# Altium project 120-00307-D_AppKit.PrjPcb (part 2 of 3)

## Sheet 6-GPIOTranslate.SchDoc: APP KIT BOARD
size 431 x 279 mm; Organization: ORGANIZATION; Address1: ADDRESS 1; Address2: ADDRESS 2; Address3: ADDRESS 3; Address4: ADDRESS 4; DocumentNumber: 6; Revision: -; SheetNumber: 6; SheetTotal: 14; ENG_APP_DATE: --/--/--; DSN_APP_DATE: --/--/--; CHK_APP_DATE: --/--/--
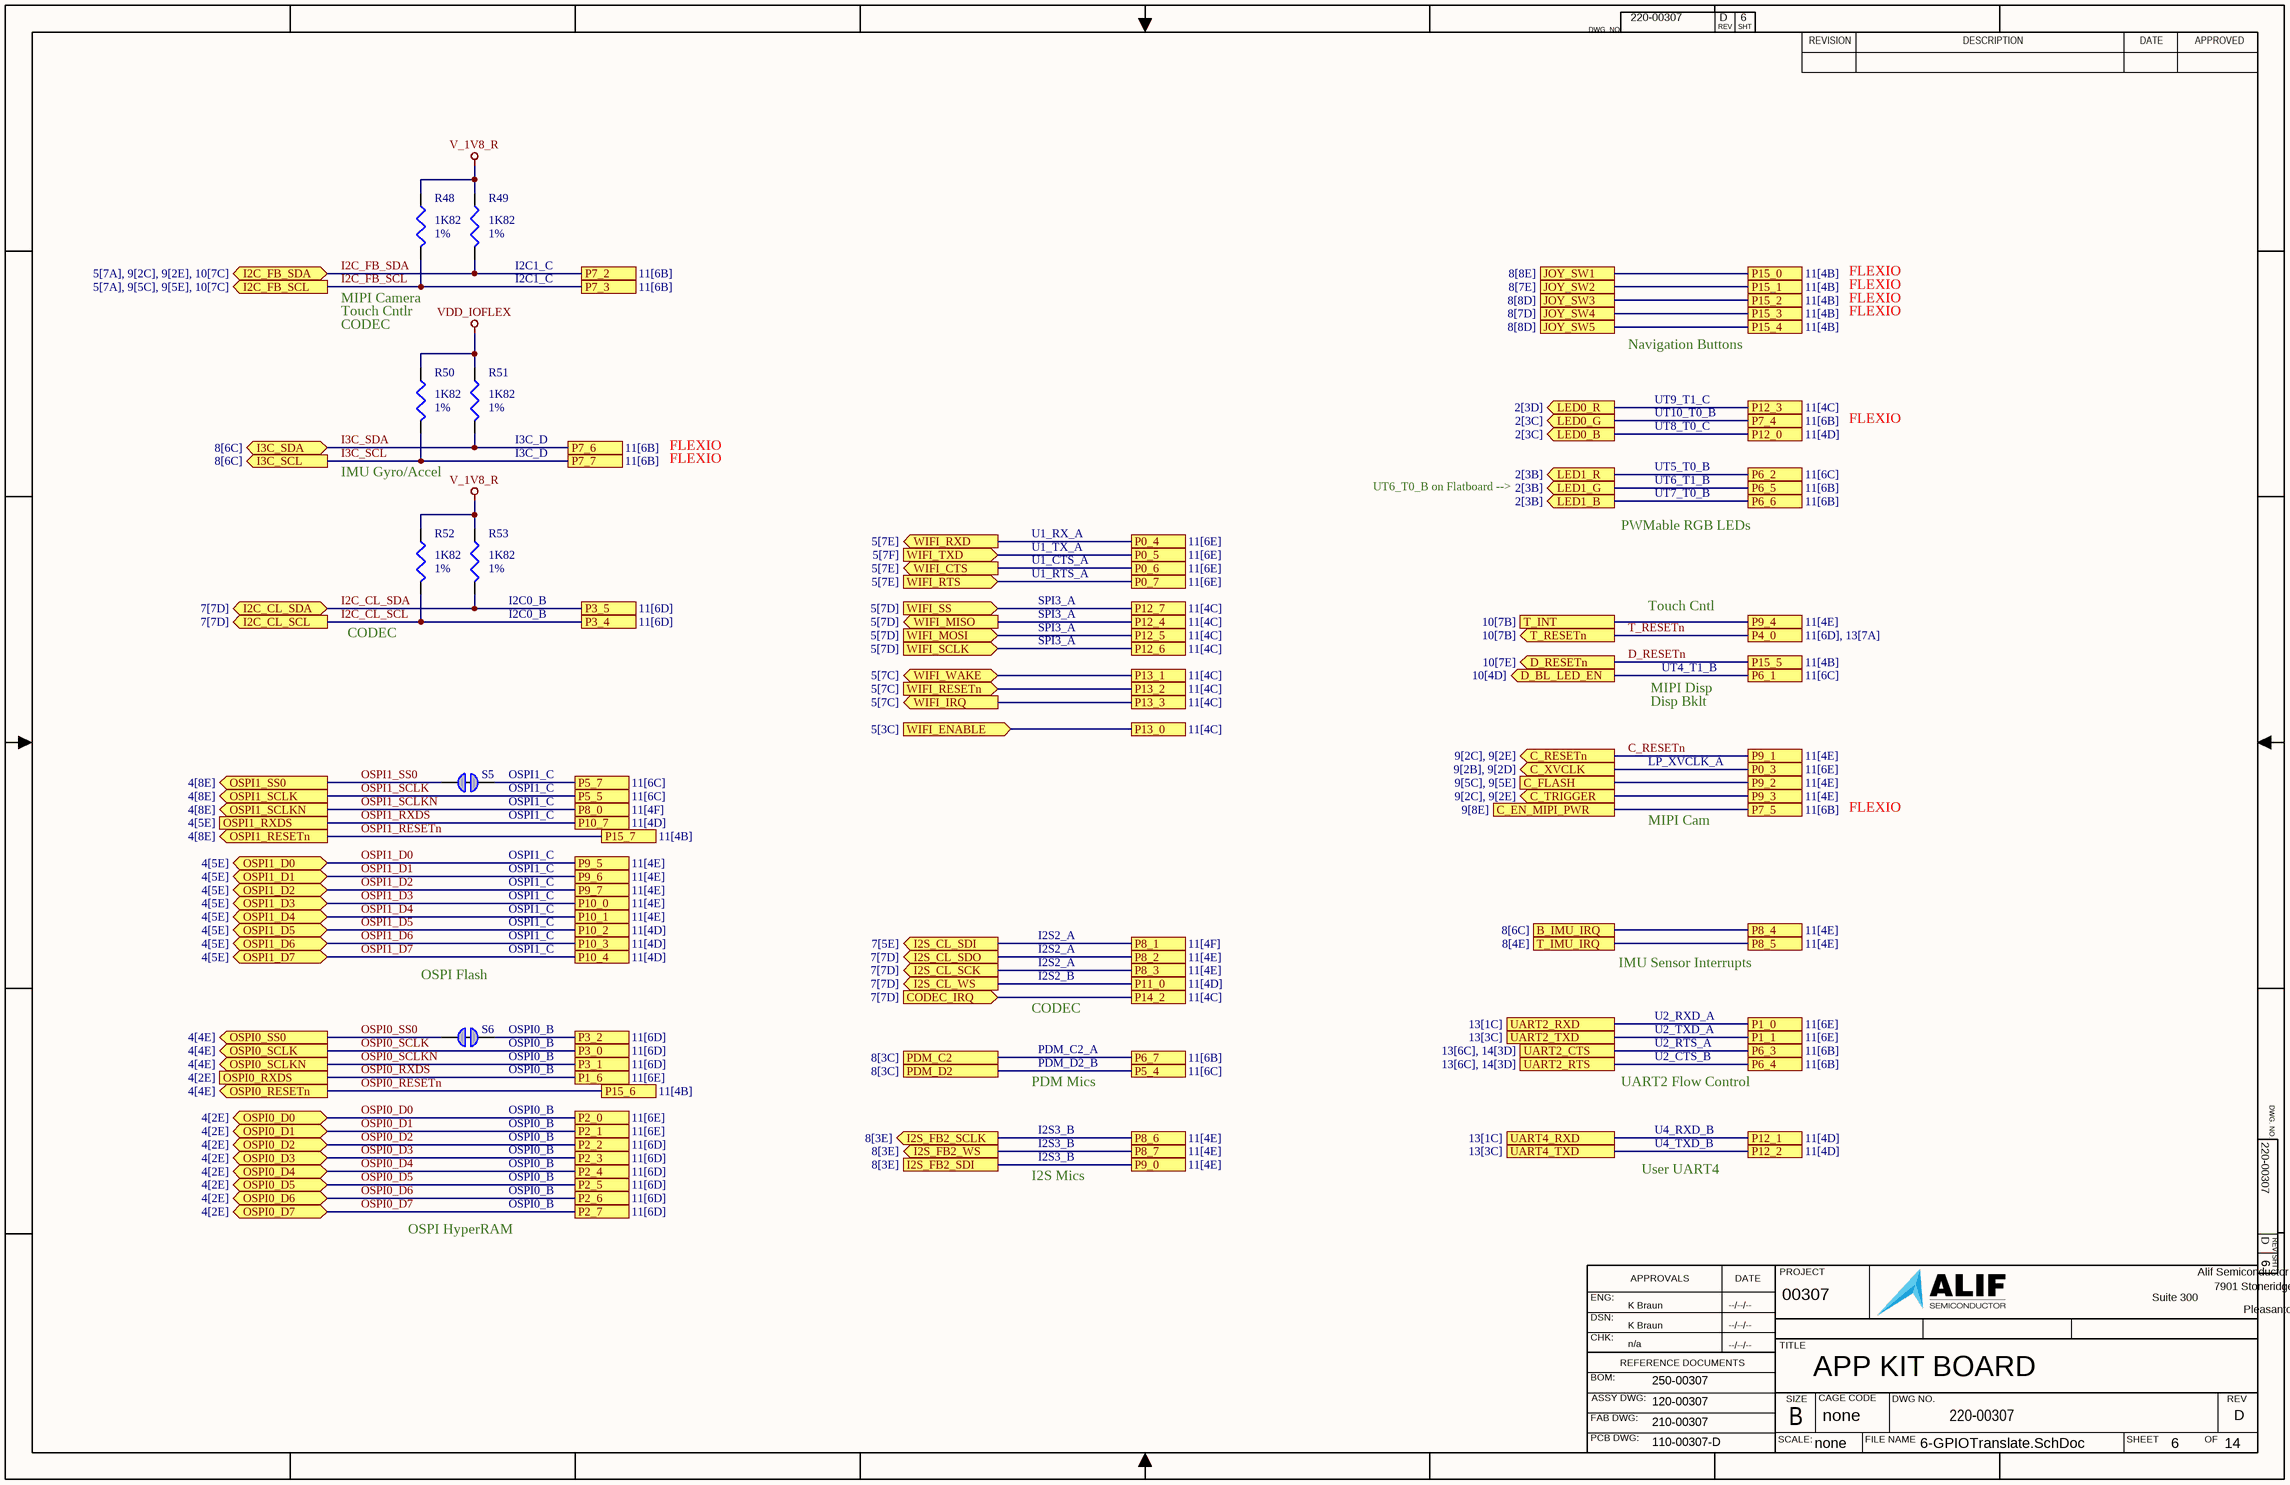
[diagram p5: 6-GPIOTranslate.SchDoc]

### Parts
R48  value 1K82  Tolerance: 1%  [RESC0402-01]  (hidden comment: Res3)
R49  value 1K82  Tolerance: 1%  [RESC0402-01]  (hidden comment: Res3)
R50  value 1K82  Tolerance: 1%  [RESC0402-01]  (hidden comment: Res3)
R51  value 1K82  Tolerance: 1%  [RESC0402-01]  (hidden comment: Res3)
R52  value 1K82  Tolerance: 1%  [RESC0402-01]  (hidden comment: Res3)
R53  value 1K82  Tolerance: 1%  [RESC0402-01]  (hidden comment: Res3)
S5  SolderJumperShorted_Small  [Solderbridge_Shorted]  (value not drawn)  (net tie, no BOM)
S6  SolderJumperShorted_Small  [Solderbridge_Shorted]  (value not drawn)  (net tie, no BOM)

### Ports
B_IMU_IRQ (see 8[6C]), C_EN_MIPI_PWR (see 9[8E]), C_FLASH (see 9[5C], 9[5E]), C_RESETn (out, see 9[2C], 9[2E]), C_TRIGGER (out, see 9[2C], 9[2E]), C_XVCLK (out, see 9[2B], 9[2D]), CODEC_IRQ (in, see 7[7D]), D_BL_LED_EN (out, see 10[4D]), D_RESETn (out, see 10[7E]), I2C_CL_SCL (out, see 7[7D]), I2C_CL_SDA (bidir, see 7[7D]), I2C_FB_SCL (out, see 5[7A], 9[5C], 9[5E], 10[7C]), I2C_FB_SDA (bidir, see 5[7A], 9[2C], 9[2E], 10[7C]), I2S_CL_SCK (out, see 7[7D]), I2S_CL_SDI (out, see 7[5E]), I2S_CL_SDO (out, see 7[7D]), I2S_CL_WS (out, see 7[7D]), I2S_FB2_SCLK (out, see 8[3E]), I2S_FB2_SDI (see 8[3E]), I2S_FB2_WS (out, see 8[3E]), I3C_SCL (out, see 8[6C]), I3C_SDA (bidir, see 8[6C]), JOY_SW1 (see 8[8E]), JOY_SW2 (see 8[7E]), JOY_SW3 (see 8[8D]), JOY_SW4 (see 8[7D]), JOY_SW5 (see 8[8D]), LED0_B (out, see 2[3C]), LED0_G (out, see 2[3C]), LED0_R (out, see 2[3D]), LED1_B (out, see 2[3B]), LED1_G (out, see 2[3B]), LED1_R (out, see 2[3B]), OSPI0_D0 (bidir, see 4[2E]), OSPI0_D1 (bidir, see 4[2E]), OSPI0_D2 (bidir, see 4[2E]), OSPI0_D3 (bidir, see 4[2E]), OSPI0_D4 (bidir, see 4[2E]), OSPI0_D5 (bidir, see 4[2E]), OSPI0_D6 (bidir, see 4[2E]), OSPI0_D7 (bidir, see 4[2E]), OSPI0_RESETn (out, see 4[4E]), OSPI0_RXDS (see 4[2E]), OSPI0_SCLK (out, see 4[4E]), OSPI0_SCLKN (out, see 4[4E]), OSPI0_SS0 (out, see 4[4E]), OSPI1_D0 (bidir, see 4[5E]), OSPI1_D1 (bidir, see 4[5E]), OSPI1_D2 (bidir, see 4[5E]), OSPI1_D3 (bidir, see 4[5E]), OSPI1_D4 (bidir, see 4[5E]), OSPI1_D5 (bidir, see 4[5E]), OSPI1_D6 (bidir, see 4[5E]), OSPI1_D7 (bidir, see 4[5E]), OSPI1_RESETn (out, see 4[8E]), OSPI1_RXDS (see 4[5E]), OSPI1_SCLK (out, see 4[8E]), OSPI1_SCLKN (out, see 4[8E]), OSPI1_SS0 (out, see 4[8E]), P0_3 (see 11[6E]), P0_4 (see 11[6E]), P0_5 (see 11[6E]), P0_6 (see 11[6E]), P0_7 (see 11[6E]), P1_0 (see 11[6E]), P1_1 (see 11[6E]), P1_6 (see 11[6E]), P2_0 (see 11[6E]), P2_1 (see 11[6E]), P2_2 (see 11[6D]), P2_3 (see 11[6D]), P2_4 (see 11[6D]), P2_5 (see 11[6D]), P2_6 (see 11[6D]), P2_7 (see 11[6D]), P3_0 (see 11[6D]), P3_1 (see 11[6D]), P3_2 (see 11[6D]), P3_4 (see 11[6D]), P3_5 (see 11[6D]), P4_0 (see 11[6D], 13[7A]), P5_4 (see 11[6C]), P5_5 (see 11[6C]), P5_7 (see 11[6C]), P6_1 (see 11[6C]), P6_2 (see 11[6C]), P6_3 (see 11[6B]), P6_4 (see 11[6B]), P6_5 (see 11[6B]), P6_6 (see 11[6B]), P6_7 (see 11[6B]), P7_2 (see 11[6B]), P7_3 (see 11[6B]), P7_4 (see 11[6B]), P7_5 (see 11[6B]), P7_6 (see 11[6B]), P7_7 (see 11[6B]), P8_0 (see 11[4F]), P8_1 (see 11[4F]), P8_2 (see 11[4E]), P8_3 (see 11[4E]), P8_4 (see 11[4E]), P8_5 (see 11[4E]), P8_6 (see 11[4E]), P8_7 (see 11[4E]), P9_0 (see 11[4E]), P9_1 (see 11[4E]), P9_2 (see 11[4E]), P9_3 (see 11[4E]), P9_4 (see 11[4E]), P9_5 (see 11[4E]), P9_6 (see 11[4E]), P9_7 (see 11[4E]), P10_0 (see 11[4E]), P10_1 (see 11[4E]), P10_2 (see 11[4D]), P10_3 (see 11[4D]), P10_4 (see 11[4D]), P10_7 (see 11[4D]), P11_0 (see 11[4D]), P12_0 (see 11[4D]), P12_1 (see 11[4D]), P12_2 (see 11[4D]), P12_3 (see 11[4C]), P12_4 (see 11[4C]), P12_5 (see 11[4C]), P12_6 (see 11[4C]), P12_7 (see 11[4C]), P13_0 (see 11[4C]), P13_1 (see 11[4C]), P13_2 (see 11[4C]), P13_3 (see 11[4C]), P14_2 (see 11[4C]), P15_0 (see 11[4B]), P15_1 (see 11[4B]), P15_2 (see 11[4B]), P15_3 (see 11[4B]), P15_4 (see 11[4B]), P15_5 (see 11[4B]), P15_6 (see 11[4B]), P15_7 (see 11[4B]), PDM_C2 (see 8[3C]), PDM_D2 (see 8[3C]), T_IMU_IRQ (see 8[4E]), T_INT (see 10[7B]), T_RESETn (out, see 10[7B]), UART2_CTS (see 13[6C], 14[3D]), UART2_RTS (see 13[6C], 14[3D]), UART2_RXD (see 13[1C]), UART2_TXD (see 13[3C]), UART4_RXD (see 13[1C]), UART4_TXD (see 13[3C]), WIFI_CTS (out, see 5[7E]), WIFI_ENABLE (in, see 5[3C]), WIFI_IRQ (out, see 5[7C]), WIFI_MISO (out, see 5[7D]), WIFI_MOSI (in, see 5[7D]), WIFI_RESETn (in, see 5[7C]), WIFI_RTS (in, see 5[7E]), WIFI_RXD (out, see 5[7E]), WIFI_SCLK (in, see 5[7D]), WIFI_SS (in, see 5[7D]), WIFI_TXD (in, see 5[7F]), WIFI_WAKE (bidir, see 5[7C])

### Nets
V_1V8_R: R48.1 R49.1 R52.1 R53.1
VDD_IOFLEX: R50.1 R51.1
C_EN_MIPI_PWR: port C_EN_MIPI_PWR, port P7_5
C_RESETn: port C_RESETn, port P9_1
D_RESETn: port D_RESETn, port P15_5
I2C_CL_SCL: R52.2 ; port P3_4, port I2C_CL_SCL
I2C_CL_SDA: R53.2 ; port I2C_CL_SDA, port P3_5
I2C_FB_SCL: R48.2 ; port P7_3, port I2C_FB_SCL
I2C_FB_SDA: R49.2 ; port I2C_FB_SDA, port P7_2
I3C_SCL: R50.2 ; port I3C_SCL, port P7_7
I3C_SDA: R51.2 ; port I3C_SDA, port P7_6
OSPI0_D0: port OSPI0_D0, port P2_0
OSPI0_D1: port OSPI0_D1, port P2_1
OSPI0_D2: port OSPI0_D2, port P2_2
OSPI0_D3: port OSPI0_D3, port P2_3
OSPI0_D4: port OSPI0_D4, port P2_4
OSPI0_D5: port OSPI0_D5, port P2_5
OSPI0_D6: port OSPI0_D6, port P2_6
OSPI0_D7: port OSPI0_D7, port P2_7
OSPI0_RESETn: port OSPI0_RESETn, port P15_6
OSPI0_RXDS: port OSPI0_RXDS, port P1_6
OSPI0_SCLK: port OSPI0_SCLK, port P3_0
OSPI0_SCLKN: port OSPI0_SCLKN, port P3_1
OSPI0_SS0: S6.1 ; port OSPI0_SS0
OSPI1_D0: port OSPI1_D0, port P9_5
OSPI1_D1: port OSPI1_D1, port P9_6
OSPI1_D2: port OSPI1_D2, port P9_7
OSPI1_D3: port OSPI1_D3, port P10_0
OSPI1_D4: port OSPI1_D4, port P10_1
OSPI1_D5: port OSPI1_D5, port P10_2
OSPI1_D6: port OSPI1_D6, port P10_3
OSPI1_D7: port OSPI1_D7, port P10_4
OSPI1_RESETn: port OSPI1_RESETn, port P15_7
OSPI1_RXDS: port OSPI1_RXDS, port P10_7
OSPI1_SCLK: port OSPI1_SCLK, port P5_5
OSPI1_SCLKN: port OSPI1_SCLKN, port P8_0
OSPI1_SS0: S5.1 ; port OSPI1_SS0
P0_3: port C_XVCLK, port P0_3
P0_4: port P0_4, port WIFI_RXD
P0_5: port P0_5, port WIFI_TXD
P0_6: port P0_6, port WIFI_CTS
P0_7: port P0_7, port WIFI_RTS
P1_0: port UART2_RXD, port P1_0
P1_1: port UART2_TXD, port P1_1
P3_2: S6.2 ; port P3_2
P5_4: port PDM_D2, port P5_4
P5_7: S5.2 ; port P5_7
P6_1: port D_BL_LED_EN, port P6_1
P6_2: port LED1_R, port P6_2
P6_3: port UART2_CTS, port P6_3
P6_4: port UART2_RTS, port P6_4
P6_5: port LED1_G, port P6_5
P6_6: port LED1_B, port P6_6
P6_7: port PDM_C2, port P6_7
P7_4: port LED0_G, port P7_4
P8_1: port I2S_CL_SDI, port P8_1
P8_2: port I2S_CL_SDO, port P8_2
P8_3: port I2S_CL_SCK, port P8_3
P8_4: port B_IMU_IRQ, port P8_4
P8_5: port T_IMU_IRQ, port P8_5
P8_6: port I2S_FB2_SCLK, port P8_6
P8_7: port I2S_FB2_WS, port P8_7
P9_0: port I2S_FB2_SDI, port P9_0
P9_2: port C_FLASH, port P9_2
P9_3: port C_TRIGGER, port P9_3
P9_4: port T_INT, port P9_4
P11_0: port I2S_CL_WS, port P11_0
P12_0: port LED0_B, port P12_0
P12_1: port UART4_RXD, port P12_1
P12_2: port UART4_TXD, port P12_2
P12_3: port LED0_R, port P12_3
P12_4: port WIFI_MISO, port P12_4
P12_5: port WIFI_MOSI, port P12_5
P12_6: port WIFI_SCLK, port P12_6
P12_7: port WIFI_SS, port P12_7
P13_0: port WIFI_ENABLE, port P13_0
P13_1: port WIFI_WAKE, port P13_1
P13_2: port WIFI_RESETn, port P13_2
P13_3: port WIFI_IRQ, port P13_3
P14_2: port CODEC_IRQ, port P14_2
P15_0: port JOY_SW1, port P15_0
P15_1: port JOY_SW2, port P15_1
P15_2: port JOY_SW3, port P15_2
P15_3: port JOY_SW4, port P15_3
P15_4: port JOY_SW5, port P15_4
T_RESETn: port T_RESETn, port P4_0  [project net P4_0]

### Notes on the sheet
- MIPI Camera
- (near R49) I2C1_C
- FLEXIO
- Touch Cntlr
- CODEC
- Navigation Buttons
- UT10_T0_B
- UT9_T1_C
- UT8_T0_C
- IMU Gyro/Accel
- (near R51) I3C_D
- UT6_T0_B on Flatboard -->
- UT5_T0_B
- UT6_T1_B
- UT7_T0_B
- U1_CTS_A
- U1_RX_A
- U1_TX_A
- PWMable RGB LEDs
- (near R53) I2C0_B
- U1_RTS_A
- SPI3_A
- Touch Cntl
- MIPI Disp
- UT4_T1_B
- LP_XVCLK_A
- Disp Bklt
- (near S5) OSPI1_C
- MIPI Cam
- OSPI1_C
- I2S2_A
- IMU Sensor Interrupts
- OSPI Flash
- (near S6) OSPI0_B
- I2S2_B
- U2_RXD_A
- U2_TXD_A
- PDM Mics
- PDM_C2_A
- PDM_D2_B
- UART2 Flow Control
- U2_CTS_B
- U2_RTS_A
- OSPI0_B
- I2S3_B
- U4_RXD_B
- U4_TXD_B
- OSPI HyperRAM
- I2S Mics
- User UART4

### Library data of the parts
R48-R53 = Res3: Res,1K82,1%,100ppm,0402; Manufacturer 1: Stackpol; Manufacturer Part Number 1: RMCF0402FT1K82; Wattage: 63mW
S5 S6 = SolderJumperShorted_Small: DNI,Solderable Jumper,Shorted; Wattage: 63mW; PCB_Footprint: SSHORTED

## Sheet 7-CODEC.SchDoc: APP KIT BOARD
size 431 x 279 mm; Organization: ORGANIZATION; Address1: ADDRESS 1; Address2: ADDRESS 2; Address3: ADDRESS 3; Address4: ADDRESS 4; DocumentNumber: 7; Revision: -; SheetNumber: 7; SheetTotal: 14; ENG_APP_DATE: --/--/--; DSN_APP_DATE: --/--/--; CHK_APP_DATE: --/--/--
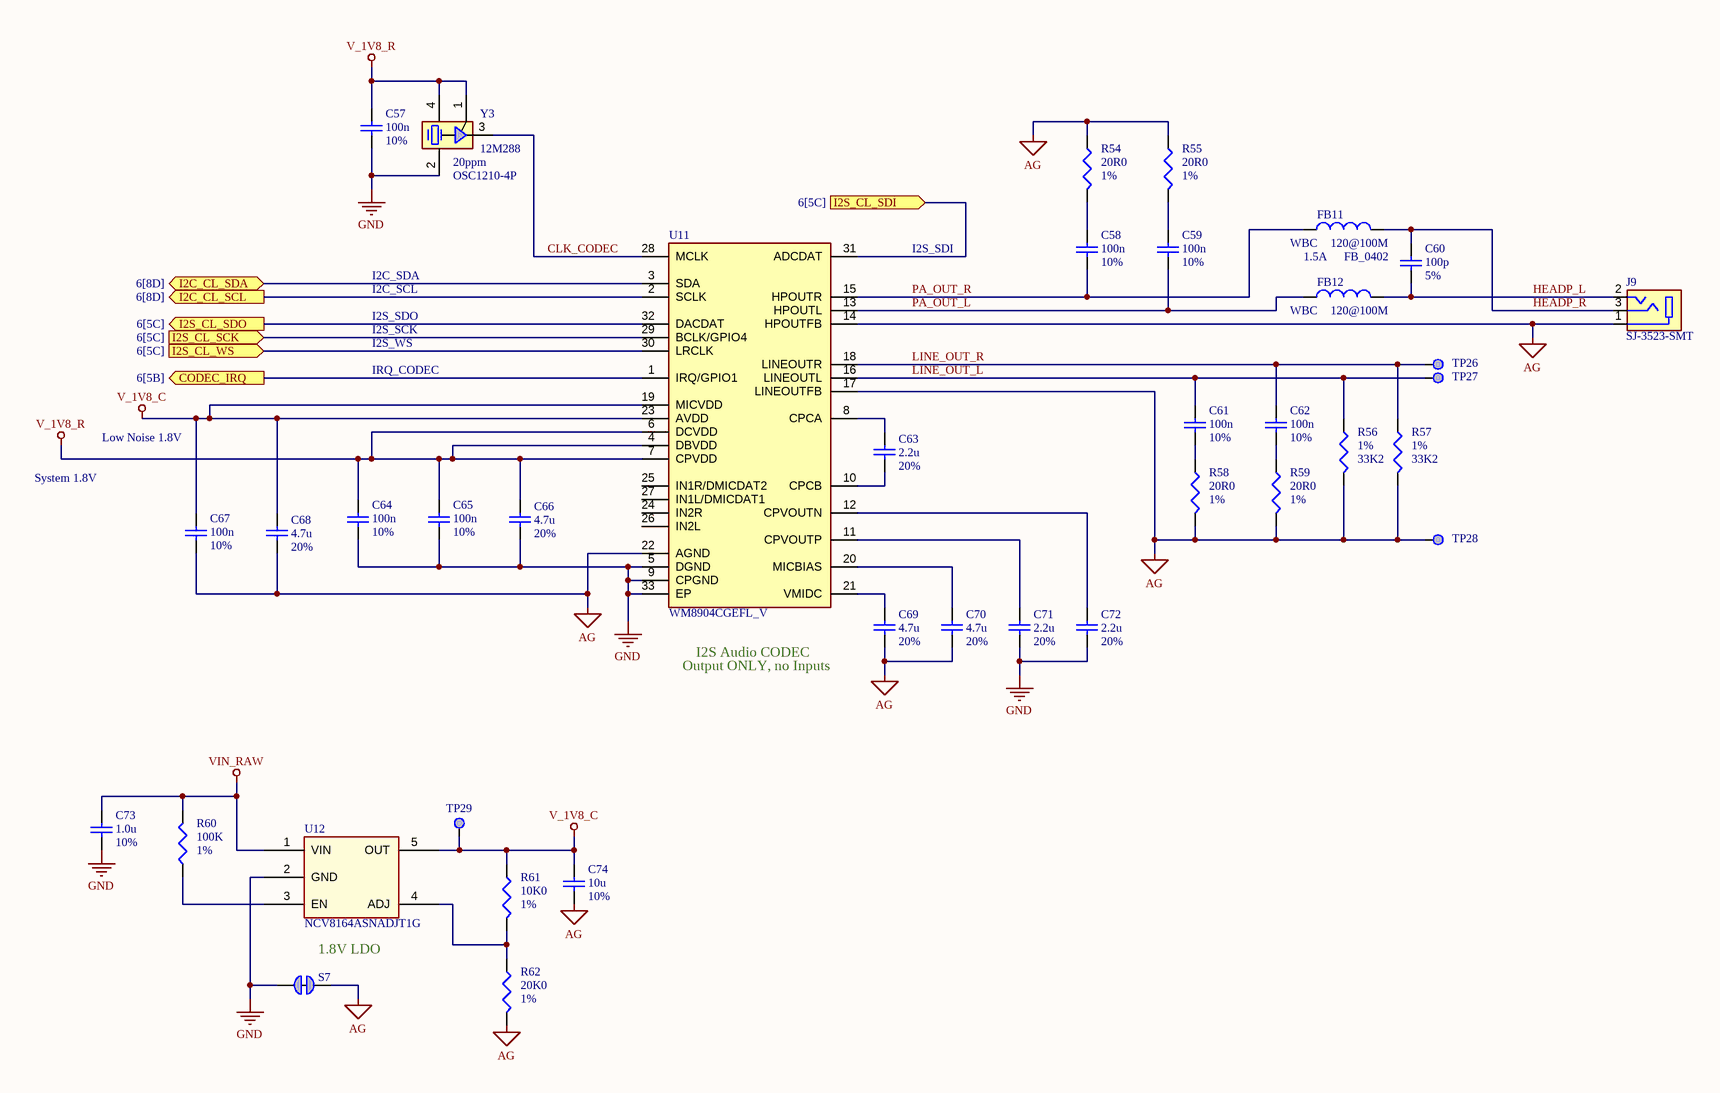
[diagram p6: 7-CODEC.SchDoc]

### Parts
C57  value 100n  Tolerance: 10%  [CAPC0402-01]  (hidden comment: Cap)
C58  value 100n  Tolerance: 10%  [CAPC0402-01]  (hidden comment: Cap)
C59  value 100n  Tolerance: 10%  [CAPC0402-01]  (hidden comment: Cap)
C60  value 100p  Tolerance: 5%  [CAPC0402-01]  (hidden comment: Cap)
C61  value 100n  Tolerance: 10%  [CAPC0402-01]  (hidden comment: Cap)
C62  value 100n  Tolerance: 10%  [CAPC0402-01]  (hidden comment: Cap)
C63  value 2.2u  Tolerance: 20%  [CAPC0402-01]  (hidden comment: Cap_225M25VX5R0402_1)
C64  value 100n  Tolerance: 10%  [CAPC0402-01]  (hidden comment: Cap)
C65  value 100n  Tolerance: 10%  [CAPC0402-01]  (hidden comment: Cap)
C66  value 4.7u  Tolerance: 20%  [CAPC0402-01]  (hidden comment: Cap)
C67  value 100n  Tolerance: 10%  [CAPC0402-01]  (hidden comment: Cap)
C68  value 4.7u  Tolerance: 20%  [CAPC0402-01]  (hidden comment: Cap)
C69  value 4.7u  Tolerance: 20%  [CAPC0402-01]  (hidden comment: Cap)
C70  value 4.7u  Tolerance: 20%  [CAPC0402-01]  (hidden comment: Cap)
C71  value 2.2u  Tolerance: 20%  [CAPC0402-01]  (hidden comment: Cap_225M25VX5R0402_1)
C72  value 2.2u  Tolerance: 20%  [CAPC0402-01]  (hidden comment: Cap_225M25VX5R0402_1)
C73  value 1.0u  Tolerance: 10%  [CAPC0402-01]  (hidden comment: Cap)
C74  value 10u  Tolerance: 10%  [CAPC0402-01]  (hidden comment: Cap)
FB11  value WBC  Impedance: 120@100M  RMS_Current: 1.5A  [FB_0402]  (hidden comment: Inductor)
FB12  value WBC  Impedance: 120@100M  [FB_0402]  (hidden comment: Inductor)
J9  SJ-3523-SMT  [CONN_CUI_SJ-3523-SMT-TR]
R54  value 20R0  Tolerance: 1%  [RESC0402-01]  (hidden comment: Res3)
R55  value 20R0  Tolerance: 1%  [RESC0402-01]  (hidden comment: Res3)
R56  value 33K2  Tolerance: 1%  [RESC0402-01]  (hidden comment: Res3)
R57  value 33K2  Tolerance: 1%  [RESC0402-01]  (hidden comment: Res3)
R58  value 20R0  Tolerance: 1%  [RESC0402-01]  (hidden comment: Res3)
R59  value 20R0  Tolerance: 1%  [RESC0402-01]  (hidden comment: Res3)
R60  value 100K  Tolerance: 1%  [RESC0402-01]  (hidden comment: Res3)
R61  value 10K0  Tolerance: 1%  [RESC0402-01]  (hidden comment: Res3)
R62  value 20K0  Tolerance: 1%  [RESC0402-01]  (hidden comment: Res3)
S7  SolderJumperShorted_Small  [Solderbridge_Shorted]  (value not drawn)  (net tie, no BOM)
TP26  TP_SMPAD  [TP_30_RND]  (value not drawn)  (no BOM)
TP27  TP_SMPAD  [TP_30_RND]  (value not drawn)  (no BOM)
TP28  TP_SMPAD  [TP_30_RND]  (value not drawn)  (no BOM)
TP29  TP_SMPAD  [TP_30_RND]  (value not drawn)  (no BOM)
U11  WM8904CGEFL_V  [QFN40P400X400X80-33N]
U12  NCV8164ASNADJT1G  [TSOT23-5_ONS]
Y3  value 12M288  Tolerance: 20ppm  PCB_Footprint: OSC1210-4P  [OSC_4P_3225_1210_uChip_DSC1001DL5]  (hidden comment: XO_12M288)

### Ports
CODEC_IRQ (out, see 6[5B]), I2C_CL_SCL (out, see 6[8D]), I2C_CL_SDA (bidir, see 6[8D]), I2S_CL_SCK (in, see 6[5C]), I2S_CL_SDI (in, see 6[5C]), I2S_CL_SDO (out, see 6[5C]), I2S_CL_WS (in, see 6[5C])

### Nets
AG: C67.1 C68.1 C69.1 C70.1 C74.1 J9.1 R54.1 R55.1 R56.2 R57.2 R58.2 R59.2 R62.2 S7.2 TP28.1 U11.14(HPOUTFB) U11.17(LINEOUTFB) U11.22(AGND)
GND: C57.1 C64.1 C65.1 C66.1 C71.1 C72.1 C73.1 S7.1 U11.5(DGND) U11.9(CPGND) U11.33(EP) U12.2(GND) Y3.2(G2)
V_1V8_C: C67.2 C68.2 C74.2 R61.1 TP29.1 U11.19(MICVDD) U11.23(AVDD) U12.5(OUT)
V_1V8_R: C57.2 C64.2 C65.2 C66.2 U11.4(DBVDD) U11.6(DCVDD) U11.7(CPVDD) Y3.1(G1) Y3.4(VDD)
VIN_RAW: C73.2 R60.2 U12.1(VIN)
CLK_CODEC: U11.28(MCLK) Y3.3(OUT)
HEADP_L: C60.1 FB12.2 J9.2
HEADP_R: C60.2 FB11.2 J9.3
I2C_CL_SCL: U11.2(SCLK) ; port I2C_CL_SCL
I2C_CL_SDA: U11.3(SDA) ; port I2C_CL_SDA
LINE_OUT_L: C61.2 R56.1 TP27.1 U11.16(LINEOUTL)
LINE_OUT_R: C62.2 R57.1 TP26.1 U11.18(LINEOUTR)
P8_1: U11.31(ADCDAT) ; port I2S_CL_SDI
P8_2: U11.32(DACDAT) ; port I2S_CL_SDO
P8_3: U11.29(BCLK/GPIO4) ; port I2S_CL_SCK
P11_0: U11.30(LRCLK) ; port I2S_CL_WS
P14_2: U11.1(IRQ/GPIO1) ; port CODEC_IRQ
PA_OUT_L: C59.1 FB12.1 U11.13(HPOUTL)
PA_OUT_R: C58.1 FB11.1 U11.15(HPOUTR)
NetC58_2: C58.2 R54.2
NetC59_2: C59.2 R55.2
NetC61_1: C61.1 R58.1
NetC62_1: C62.1 R59.1
NetC63_1: C63.1 U11.10(CPCB)
NetC63_2: C63.2 U11.8(CPCA)
NetC69_2: C69.2 U11.21(VMIDC)
NetC70_2: C70.2 U11.20(MICBIAS)
NetC71_2: C71.2 U11.11(CPVOUTP)
NetC72_2: C72.2 U11.12(CPVOUTN)
NetR60_1: R60.1 U12.3(EN)
NetR61_2: R61.2 R62.1 U12.4(ADJ)

Not connected (* = marked no-connect by the designer): U11 24(IN2R) 25(IN1R/DMICDAT2) 26(IN2L) 27(IN1L/DMICDAT1)

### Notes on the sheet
- I2C_SDA
- I2S_SDI
- I2S_SCK
- I2S_WS
- I2S_SDO
- I2C_SCL
- IRQ_CODEC
- System 1.8V
- Low Noise 1.8V
- Output ONLY, no Inputs
- I2S Audio CODEC
- 1.8V LDO

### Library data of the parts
C57-C59 C61 C62 C64 C65 C67 = Cap: Cap,100nF,10%,50V,X7R,0402; Manufacturer 1: TDK; Manufacturer Part Number 1: C1005X7R1H104K050BE; PCB_Footprint: CC0402
C60 = Cap: Cap,100pF,5%,25V,C0G,Hi-Q,0402; Manufacturer 1: Kemet; Manufacturer Part Number 1: CBR04C101J3GAC; PCB_Footprint: CC0402
C63 C71 C72 = Cap_225M25VX5R0402_1: Cap,2.2uF,20%,25V,X5R,0402; Manufacturer 1: TDK; Manufacturer Part Number 1: C1005X5R1E225M050BC; PCB_Footprint: CC0402
C66 C68-C70 = Cap_225M25VX5R0402_1: Cap,4.7uF,20%,10V,X5R,0402; Manufacturer 1: TDK; Manufacturer Part Number 1: C1005X5R1A475K050BC; PCB_Footprint: CC0402
C73 = Cap: Cap,1.0uF,20%,25V,X5R,0402; Manufacturer 1: TDK; Manufacturer Part Number 1: CGB2A1X5R1E105K033BC; PCB_Footprint: CC0402
C74 = Cap: Cap,10uF,20%,10V,X5R,0402; Manufacturer 1: AVX; Manufacturer Part Number 1: 0402ZD106MAT2A; PCB_Footprint: CC0402
FB11 FB12 = Inductor: Ind,WidebandChoke,1.5A,120ohm@100MHz,95mOhm,0402; Manufacturer 1: MuRata; Manufacturer Part Number 1: BLM15EG121SN1D; Code_IEC: 1005
J9 = CONN_AUDIO_SJ-3523-SMT-TR: Conn, Audio Jack, 3.5 mm Low Profile Surface Mount Stereo Jack, 3 Pin Right-Angle; Manufacturer 1: CUI
R54 R55 R58 R59 = Res3: Res,20R0,1%,100ppm,0402; Manufacturer 1: Stackpol; Manufacturer Part Number 1: RMCF0402FT20R; Wattage: 63mW; PCB_Footprint: R0402
R56 R57 = Res3: Res,33K2,1%,100ppm,0402; Manufacturer 1: Stackpol; Manufacturer Part Number 1: RMCF0402FT33K2; Wattage: 63mW
R60 = Res3: Res,100K,1%,100ppm,0402; Manufacturer 1: Stackpol; Manufacturer Part Number 1: RMCF0402FT100K; Wattage: 63mW
R61 = Res3: Res,10K0,1%,100ppm,0402; Manufacturer 1: Stackpol; Manufacturer Part Number 1: RMCF0402FT10K0; Wattage: 63mW; PCB_Footprint: R0402
R62 = Res3: Res,20K0,1%,100ppm,0402; Manufacturer 1: Stackpol; Manufacturer Part Number 1: RMCF0402FT20K0; Wattage: 63mW
S7 = SolderJumperShorted_Small: as S5 on sheet 6-GPIOTranslate
TP26-TP29 = TP_SMPAD: Test Point, SMT Pad,--not a BOM item--; PCB_Footprint: TP_PAD1
U11 = IC_CODEC_WM8904CGEFL_V: IC, Audio CODEC, Ultra Low Pwr, 1.8V, QFN33; Manufacturer 1: Cirrus Logic; Manufacturer Part Number 1: WM8904CGEFL/V; Geometry.Height: 0.8mm
U12 = IC_LDO_NCV8164ASNADJT1G: IC, LDO,Adj 1.2V - 5.5V,300mA,SOT23-5; Manufacturer 1: OnSemi
Y3 = Osc_12M288_20ppm_1V8_3225: Oscillator,XO,12.288MHz,20ppm,1.8V,3225(1210)-4P; Manufacturer 1: Microchip; Manufacturer Part Number 1: DSC1001DL5-012.2880

## Sheet 8-Sensors.SchDoc: APP KIT BOARD
size 431 x 279 mm; Organization: ORGANIZATION; Address1: ADDRESS 1; Address2: ADDRESS 2; Address3: ADDRESS 3; Address4: ADDRESS 4; DocumentNumber: 8; Revision: -; SheetNumber: 8; SheetTotal: 14; ENG_APP_DATE: --/--/--; DSN_APP_DATE: --/--/--; CHK_APP_DATE: --/--/--
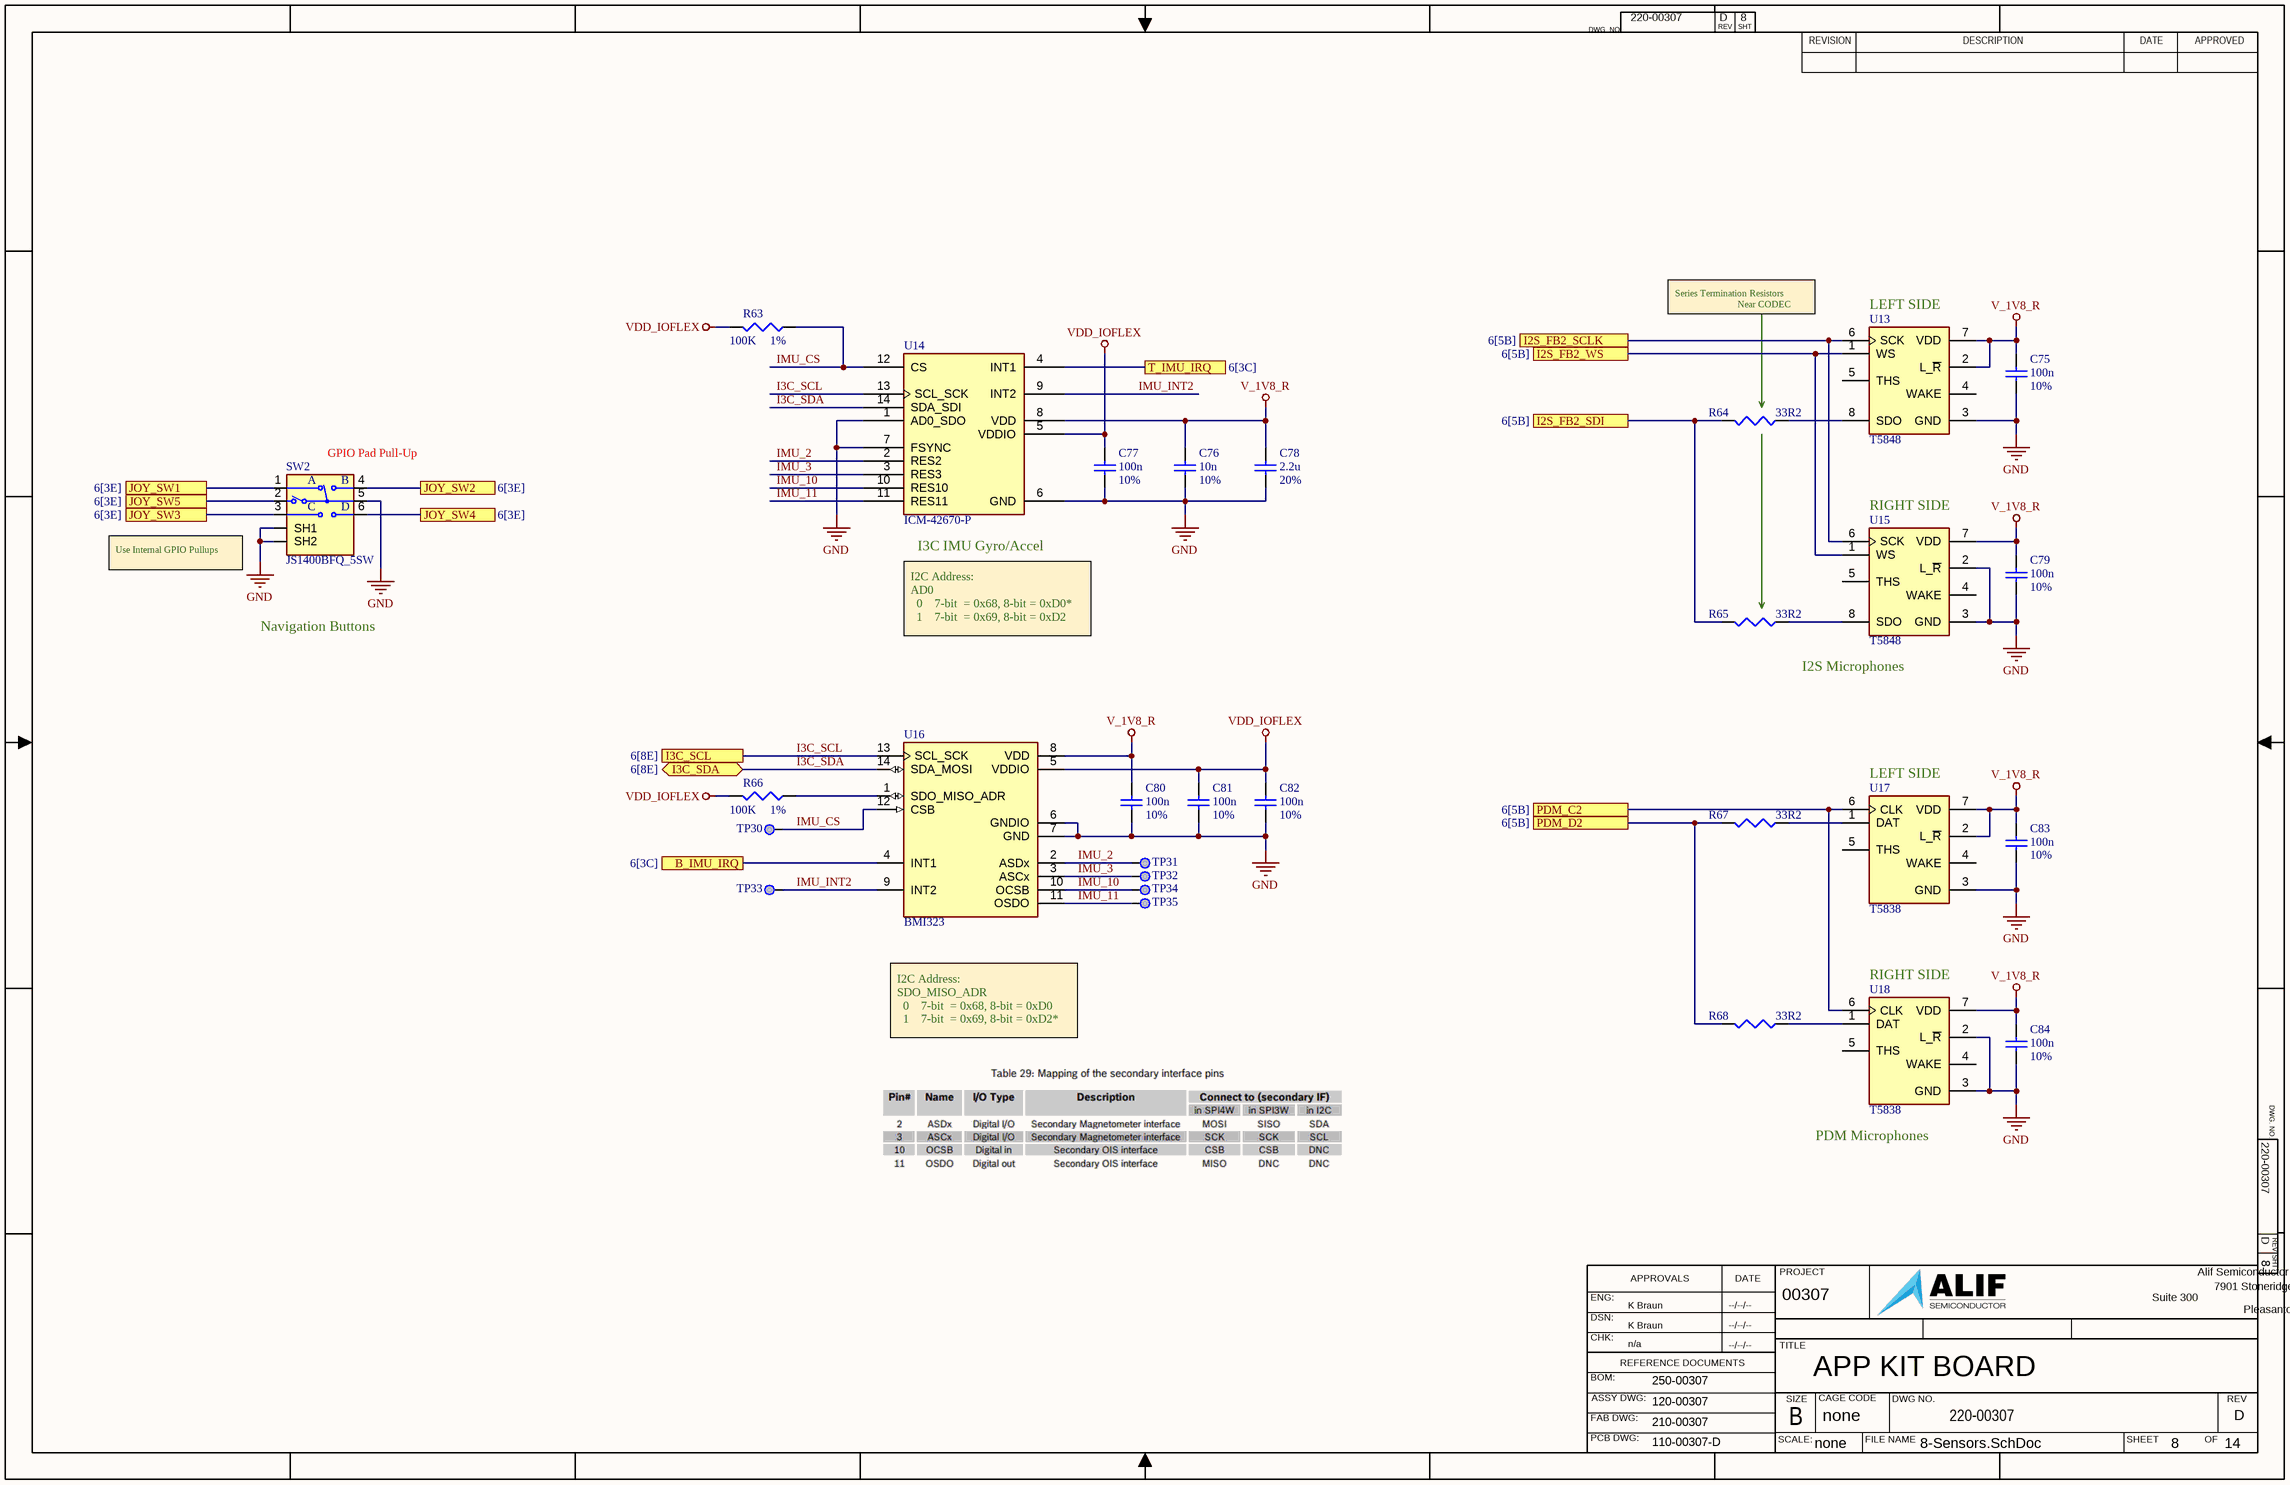
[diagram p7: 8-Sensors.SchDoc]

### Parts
C75  value 100n  Tolerance: 10%  [CAPC0402-01]  (hidden comment: Cap)
C76  value 10n  Tolerance: 10%  [CAPC0402-01]  (hidden comment: Cap)
C77  value 100n  Tolerance: 10%  [CAPC0402-01]  (hidden comment: Cap)
C78  value 2.2u  Tolerance: 20%  [CAPC0402-01]  (hidden comment: Cap_225M25VX5R0402_1)
C79  value 100n  Tolerance: 10%  [CAPC0402-01]  (hidden comment: Cap)
C80  value 100n  Tolerance: 10%  [CAPC0402-01]  (hidden comment: Cap)
C81  value 100n  Tolerance: 10%  [CAPC0402-01]  (hidden comment: Cap)
C82  value 100n  Tolerance: 10%  [CAPC0402-01]  (hidden comment: Cap)
C83  value 100n  Tolerance: 10%  [CAPC0402-01]  (hidden comment: Cap)
C84  value 100n  Tolerance: 10%  [CAPC0402-01]  (hidden comment: Cap)
R63  value 100K  Tolerance: 1%  [RESC0402-01]  (hidden comment: Res3)
R64  value 33R2  [RESC0402-01]  (hidden comment: Res3)
R65  value 33R2  [RESC0402-01]  (hidden comment: Res3)
R66  value 100K  Tolerance: 1%  [RESC0402-01]  (hidden comment: Res3)
R67  value 33R2  [RESC0402-01]  (hidden comment: Res3)
R68  value 33R2  [RESC0402-01]  (hidden comment: Res3)
SW2  JS1400BFQ_5SW  [SW_JS1400BFQ]
TP30  TP_SMPAD  [TP_30_RND]  (value not drawn)  (no BOM)
TP31  TP_SMPAD  [TP_30_RND]  (value not drawn)  (no BOM)
TP32  TP_SMPAD  [TP_30_RND]  (value not drawn)  (no BOM)
TP33  TP_SMPAD  [TP_30_RND]  (value not drawn)  (no BOM)
TP34  TP_SMPAD  [TP_30_RND]  (value not drawn)  (no BOM)
TP35  TP_SMPAD  [TP_30_RND]  (value not drawn)  (no BOM)
U13  T5848  [mic_T5848]
U14  Manufacturer Part Number 1: ICM-42670-P  [IC_ICM-42670-P]  (hidden comment: ICM-42670-P_1)
U15  T5848  [mic_T5848]
U16  BMI323  [PQFN50P250X300X88-14N]
U17  T5838  [MIC_T5838]
U18  T5838  [MIC_T5838]

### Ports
B_IMU_IRQ (see 6[3C]), I2S_FB2_SCLK (see 6[5B]), I2S_FB2_SDI (see 6[5B]), I2S_FB2_WS (see 6[5B]), I3C_SCL (see 6[8E]), I3C_SDA (bidir, see 6[8E]), JOY_SW1 (see 6[3E]), JOY_SW2 (see 6[3E]), JOY_SW3 (see 6[3E]), JOY_SW4 (see 6[3E]), JOY_SW5 (see 6[3E]), PDM_C2 (see 6[5B]), PDM_D2 (see 6[5B]), T_IMU_IRQ (see 6[3C])

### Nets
GND: C75.2 C76.1 C77.2 C78.1 C79.2 C80.2 C81.2 C82.2 C83.2 C84.2 SW2.5(COM) SW2.SH1 SW2.SH2 U13.3(GND) U14.1(AD0_SDO) U14.6(GND) U14.7(FSYNC) U15.2(L_~{R}) U15.3(GND) U16.6(GNDIO) U16.7(GND) U17.3(GND) U18.2(L_~{R}) U18.3(GND)
V_1V8_R: C75.1 C76.2 C78.2 C79.1 C80.1 C83.1 C84.1 U13.2(L_~{R}) U13.7(VDD) U14.8(VDD) U15.7(VDD) U16.8(VDD) U17.2(L_~{R}) U17.7(VDD) U18.7(VDD)
VDD_IOFLEX: C77.1 C81.1 C82.1 R63.2 R66.2 U14.5(VDDIO) U16.5(VDDIO)
I3C_SCL: U14.13(SCL_SCK) U16.13(SCL_SCK) ; port I3C_SCL
I3C_SDA: U14.14(SDA_SDI) U16.14(SDA_MOSI) ; port I3C_SDA
IMU_2: TP31.1 U14.2(RES2) U16.2(ASDx)
IMU_3: TP32.1 U14.3(RES3) U16.3(ASCx)
IMU_10: TP34.1 U14.10(RES10) U16.10(OCSB)
IMU_11: TP35.1 U14.11(RES11) U16.11(OSDO)
IMU_CS: R63.1 TP30.1 U14.12(CS) U16.12(CSB)
IMU_INT2: TP33.1 U14.9(INT2) U16.9(INT2)
P5_4: R67.2 R68.2 ; port PDM_D2
P6_7: U17.6(CLK) U18.6(CLK) ; port PDM_C2
P8_4: U16.4(INT1) ; port B_IMU_IRQ
P8_5: U14.4(INT1) ; port T_IMU_IRQ
P8_6: U13.6(SCK) U15.6(SCK) ; port I2S_FB2_SCLK
P8_7: U13.1(WS) U15.1(WS) ; port I2S_FB2_WS
P9_0: R64.2 R65.2 ; port I2S_FB2_SDI
P15_0: SW2.1(A) ; port JOY_SW1
P15_1: SW2.4(B) ; port JOY_SW2
P15_2: SW2.3(C) ; port JOY_SW3
P15_3: SW2.6(D) ; port JOY_SW4
P15_4: SW2.2(E) ; port JOY_SW5
NetR64_1: R64.1 U13.8(SDO)
NetR65_1: R65.1 U15.8(SDO)
NetR66_1: R66.1 U16.1(SDO_MISO_ADR)
NetR67_1: R67.1 U17.1(DAT)
NetR68_1: R68.1 U18.1(DAT)

Not connected (* = marked no-connect by the designer): U13 4(WAKE) 5(THS); U15 4(WAKE) 5(THS); U17 4(WAKE) 5(THS); U18 4(WAKE) 5(THS)

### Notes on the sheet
- Series Termination Resistors
  Near CODEC
- (near U13) LEFT SIDE
- (near SW2) GPIO Pad Pull-Up
- (near SW2) Use Internal GPIO Pullups
- (near U14) I3C IMU Gyro/Accel
- (near U15) RIGHT SIDE
- Navigation Buttons
- I2C Address:
  AD0
  0    7-bit  = 0x68, 8-bit = 0xD0*
  1    7-bit  = 0x69, 8-bit = 0xD2
- I2S Microphones
- (near U17) LEFT SIDE
- I2C Address:
  SDO_MISO_ADR
  0    7-bit  = 0x68, 8-bit = 0xD0
  1    7-bit  = 0x69, 8-bit = 0xD2*
- (near U18) RIGHT SIDE
- (near U18) PDM Microphones

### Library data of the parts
C75 C77 C79-C84 = Cap: as C57-C59 on sheet 7-CODEC
C76 = Cap: Cap,10nF,10%,50V,X7R,0402; Manufacturer 1: TDK; Manufacturer Part Number 1: CGA2B3X7R1H103K050BE; PCB_Footprint: CC0402
C78 = Cap_225M25VX5R0402_1: as C63 on sheet 7-CODEC
R63 R66 = Res3: as R60 on sheet 7-CODEC
R64 R65 R67 R68 = Res3: Res,33R2,1%,100ppm,0402; Manufacturer 1: Stackpol; Manufacturer Part Number 1: RMCF0402FT33R2; Wattage: 63mW
SW2 = JS1400BFQ_5SW: Navigation Switch, 2 - Axis Digital (Mechanical Switch) Output; Manufacturer 1: ESwitch; MF: E-Switch
TP30-TP35 = TP_SMPAD: as TP26-TP29 on sheet 7-CODEC
U13 = MIC_T5848: IC,Microphone,I2S,Bottom Port,Sens -37db,SNR 68dbA,AOP 13db SPL,1.8V; Manufacturer_Name: TDK; Manufacturer 1: TDK/Invensense; Manufacturer Part Number 1: T5848-00-012
U14 = ICM-42670-P_1: IC, IMU Gyro & Accel, I3C, 1.8V, LGA14; Manufacturer 1: TDK_Invensense; Value: Gyro_Accel
U15 = MIC_T5848: IC,Microphone,I2S,Bottom Port,Sens -37db,SNR 68dbA,AOP 13db SPL,1.8V; Manufacturer_Name: TDK; Manufacturer_Part_Number: T5848-00-012; Manufacturer 1: TDK/Invensense
U16 = IC_IMU_BMI323: IC,IMU,6 Axis Sensor I3C, SPI, LGA14; MF: Bosch
U17 U18 = MIC_T5838: IC,Microphone,PDM,Bottom Port,Sens -37db,SNR 68dbA,AOP 13db SPL,1.8V; Manufacturer 1: TDK; Manufacturer Part Number 1: MMICT5838-00-012; Value: PDM Mic

## Sheet 9-MIPI_CSI.SchDoc: APP KIT BOARD
size 431 x 279 mm; Organization: ORGANIZATION; Address1: ADDRESS 1; Address2: ADDRESS 2; Address3: ADDRESS 3; Address4: ADDRESS 4; DocumentNumber: 9; Revision: -; SheetNumber: 9; SheetTotal: 14; ENG_APP_DATE: --/--/--; DSN_APP_DATE: --/--/--; CHK_APP_DATE: --/--/--
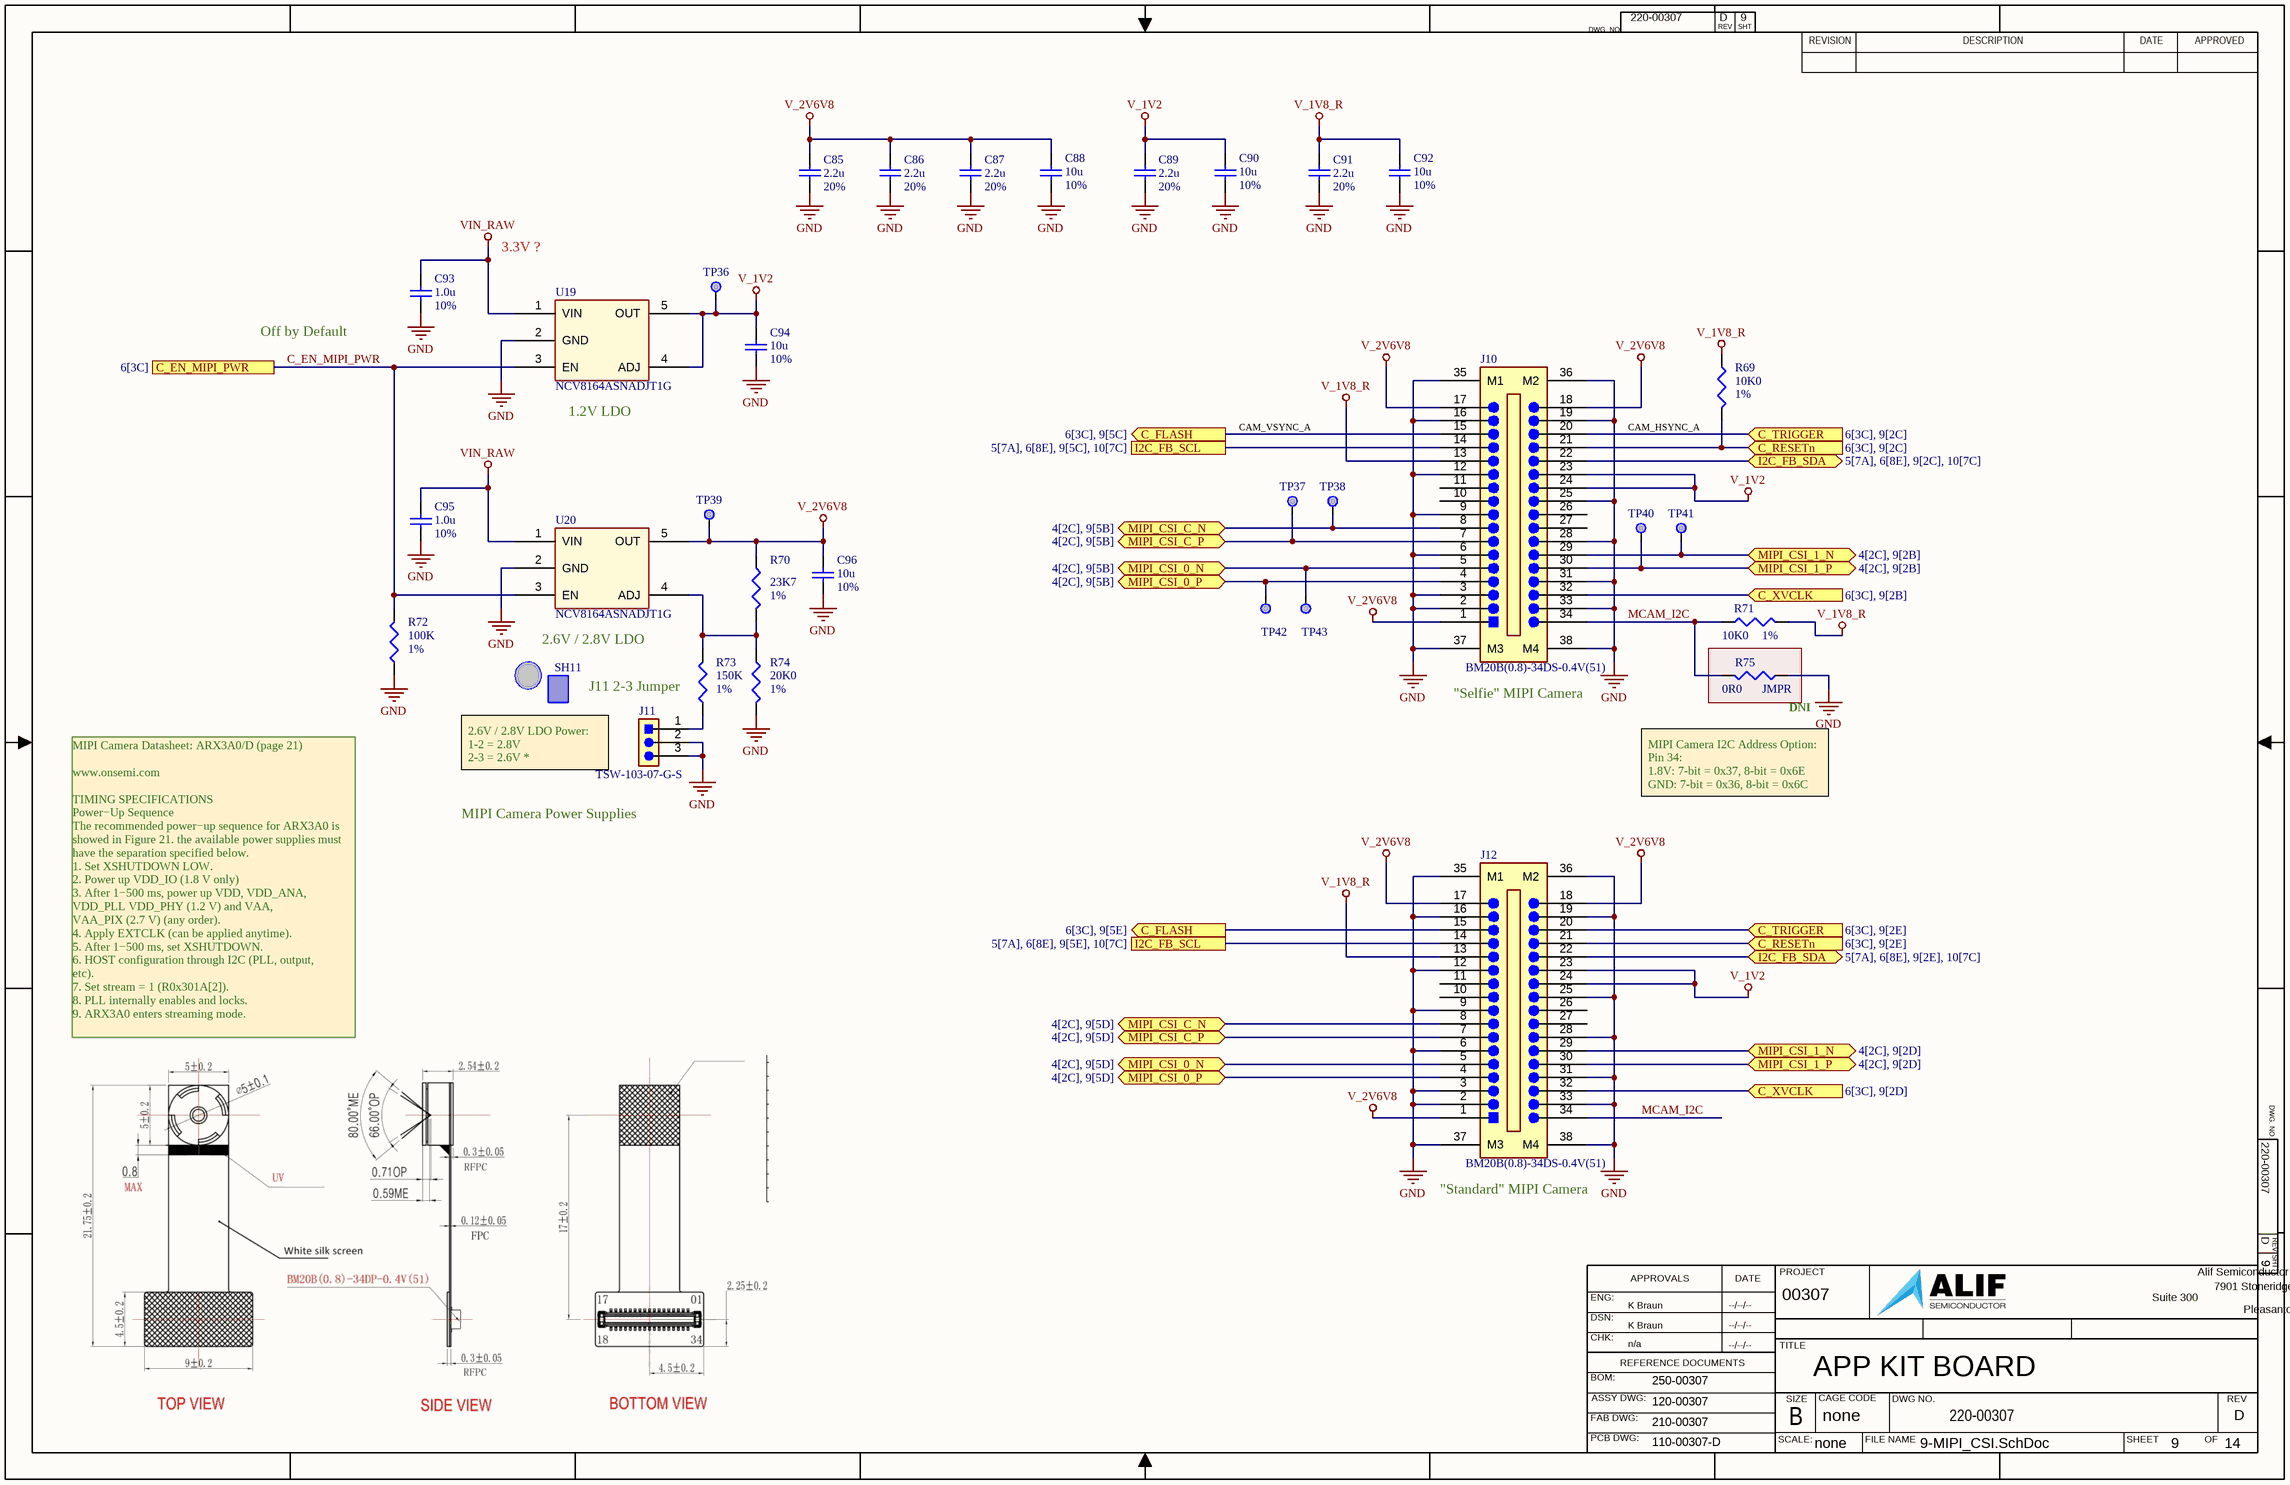
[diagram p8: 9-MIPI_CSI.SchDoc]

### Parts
C85  value 2.2u  Tolerance: 20%  [CAPC0402-01]  (hidden comment: Cap_225M25VX5R0402_1)
C86  value 2.2u  Tolerance: 20%  [CAPC0402-01]  (hidden comment: Cap_225M25VX5R0402_1)
C87  value 2.2u  Tolerance: 20%  [CAPC0402-01]  (hidden comment: Cap_225M25VX5R0402_1)
C88  value 10u  Tolerance: 10%  [CAPC0402-01]  (hidden comment: Cap)
C89  value 2.2u  Tolerance: 20%  [CAPC0402-01]  (hidden comment: Cap_225M25VX5R0402_1)
C90  value 10u  Tolerance: 10%  [CAPC0402-01]  (hidden comment: Cap)
C91  value 2.2u  Tolerance: 20%  [CAPC0402-01]  (hidden comment: Cap_225M25VX5R0402_1)
C92  value 10u  Tolerance: 10%  [CAPC0402-01]  (hidden comment: Cap)
C93  value 1.0u  Tolerance: 10%  [CAPC0402-01]  (hidden comment: Cap)
C94  value 10u  Tolerance: 10%  [CAPC0402-01]  (hidden comment: Cap)
C95  value 1.0u  Tolerance: 10%  [CAPC0402-01]  (hidden comment: Cap)
C96  value 10u  Tolerance: 10%  [CAPC0402-01]  (hidden comment: Cap)
J10  BM20B(0.8)-34DS-0.4V(51)  [CONN_FPC_BM20B0834DS04V51_W/MODULE]
J11  TSW-103-07-G-S  [CONN_HDR_1X3_STRT_0.100]
J12  BM20B(0.8)-34DS-0.4V(51)  [CONN_FPC_BM20B0834DS04V51_W/MODULE]
R69  value 10K0  Tolerance: 1%  [RESC0402-01]  (hidden comment: Res3)
R70  value 23K7  Tolerance: 1%  [RESC0402-01]  (hidden comment: Res3)
R71  value 10K0  Tolerance: 1%  [RESC0402-01]  (hidden comment: Res3)
R72  value 100K  Tolerance: 1%  [RESC0402-01]  (hidden comment: Res3)
R73  value 150K  Tolerance: 1%  [RESC0402-01]  (hidden comment: Res3)
R74  value 20K0  Tolerance: 1%  [RESC0402-01]  (hidden comment: Res3)
R75  value 0R0  Tolerance: JMPR  [RESC0402-01]  (hidden comment: Res3)
SH11  Shunt  (value not drawn)  (mechanical)
TP36  TP_SMPAD  [TP_30_RND]  (value not drawn)  (no BOM)
TP37  TP_SMPAD  [TP_30_RND]  (value not drawn)  (no BOM)
TP38  TP_SMPAD  [TP_30_RND]  (value not drawn)  (no BOM)
TP39  TP_SMPAD  [TP_30_RND]  (value not drawn)  (no BOM)
TP40  TP_SMPAD  [TP_30_RND]  (value not drawn)  (no BOM)
TP41  TP_SMPAD  [TP_30_RND]  (value not drawn)  (no BOM)
TP42  TP_SMPAD  [TP_30_RND]  (value not drawn)  (no BOM)
TP43  TP_SMPAD  [TP_30_RND]  (value not drawn)  (no BOM)
U19  NCV8164ASNADJT1G  [TSOT23-5_ONS]
U20  NCV8164ASNADJT1G  [TSOT23-5_ONS]

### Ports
C_EN_MIPI_PWR (see 6[3C]), C_FLASH (out, see 6[3C], 9[5C]), C_FLASH (out, see 6[3C], 9[5E]), C_RESETn (in, see 6[3C], 9[2C]), C_RESETn (in, see 6[3C], 9[2E]), C_TRIGGER (in, see 6[3C], 9[2C]), C_TRIGGER (in, see 6[3C], 9[2E]), C_XVCLK (in, see 6[3C], 9[2B]), C_XVCLK (in, see 6[3C], 9[2D]), I2C_FB_SCL (see 5[7A], 6[8E], 9[5C], 10[7C]), I2C_FB_SCL (see 5[7A], 6[8E], 9[5E], 10[7C]), I2C_FB_SDA (bidir, see 5[7A], 6[8E], 9[2C], 10[7C]), I2C_FB_SDA (bidir, see 5[7A], 6[8E], 9[2E], 10[7C]), MIPI_CSI_0_N (bidir, see 4[2C], 9[5B]), MIPI_CSI_0_N (bidir, see 4[2C], 9[5D]), MIPI_CSI_0_P (bidir, see 4[2C], 9[5B]), MIPI_CSI_0_P (bidir, see 4[2C], 9[5D]), MIPI_CSI_1_N (bidir, see 4[2C], 9[2B]), MIPI_CSI_1_N (bidir, see 4[2C], 9[2D]), MIPI_CSI_1_P (bidir, see 4[2C], 9[2B]), MIPI_CSI_1_P (bidir, see 4[2C], 9[2D]), MIPI_CSI_C_N (bidir, see 4[2C], 9[5B]), MIPI_CSI_C_N (bidir, see 4[2C], 9[5D]), MIPI_CSI_C_P (bidir, see 4[2C], 9[5B]), MIPI_CSI_C_P (bidir, see 4[2C], 9[5D])

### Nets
GND: C85.1 C86.1 C87.1 C88.1 C89.1 C90.1 C91.1 C92.1 C93.1 C94.1 C95.1 C96.1 J10.2 J10.3 J10.6 J10.9 J10.12 J10.16 J10.19 J10.25 J10.28 J10.31 J10.33 J10.35(M1) J10.36(M2) J10.37(M3) J10.38(M4) J11.2 J11.3 J12.2 J12.3 J12.6 J12.9 J12.12 J12.16 J12.19 J12.25 J12.28 J12.31 J12.33 J12.35(M1) J12.36(M2) J12.37(M3) J12.38(M4) R72.1 R74.2 R75.1 U19.2(GND) U20.2(GND)
V_1V2: C89.2 C90.2 C94.2 J10.23 J10.24 J12.23 J12.24 TP36.1 U19.4(ADJ) U19.5(OUT)
V_1V8_R: C91.2 C92.2 J10.13 J12.13 R69.1 R71.2
V_2V6V8: C85.2 C86.2 C87.2 C88.2 C96.2 J10.1 J10.17 J10.18 J12.1 J12.17 J12.18 R70.1 TP39.1 U20.5(OUT)
VIN_RAW: C93.2 C95.2 U19.1(VIN) U20.1(VIN)
C_EN_MIPI_PWR: R72.2 U19.3(EN) U20.3(EN) ; port C_EN_MIPI_PWR
C_RESETn: J10.21 J12.21 R69.2 ; port C_RESETn
I2C_FB_SCL: J10.14 J12.14 ; port I2C_FB_SCL
I2C_FB_SDA: J10.22 J12.22 ; port I2C_FB_SDA
MCAM_I2C: J10.34 J12.34 R71.1 R75.2
MIPI_CSI_0_N: J10.5 J12.5 TP43.1 ; port MIPI_CSI_0_N
MIPI_CSI_0_P: J10.4 J12.4 TP42.1 ; port MIPI_CSI_0_P
MIPI_CSI_1_N: J10.29 J12.29 TP41.1 ; port MIPI_CSI_1_N
MIPI_CSI_1_P: J10.30 J12.30 TP40.1 ; port MIPI_CSI_1_P
MIPI_CSI_C_N: J10.8 J12.8 TP38.1 ; port MIPI_CSI_C_N
MIPI_CSI_C_P: J10.7 J12.7 TP37.1 ; port MIPI_CSI_C_P
P0_3: J10.32 J12.32 ; port C_XVCLK
P9_2: J10.15 J12.15 ; port C_FLASH
P9_3: J10.20 J12.20 ; port C_TRIGGER
NetJ11_1: J11.1 R73.1
NetR70_2: R70.2 R73.2 R74.1 U20.4(ADJ)

Not connected (* = marked no-connect by the designer): J10 10 11 26 27; J12 10 11 26 27

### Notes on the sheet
- 3.3V ?
- Off by Default
- (near U19) 1.2V LDO
- CAM_VSYNC_A
- (near R69) CAM_HSYNC_A
- 2.6V / 2.8V LDO
- (near R73) J11 2-3 Jumper
- (near J10) "Selfie" MIPI Camera
- (near SH11) 2.6V / 2.8V LDO Power:
  1-2 = 2.8V
  2-3 = 2.6V *
- (near R75) DNI
- (near J11) MIPI Camera Power Supplies
- MIPI Camera I2C Address Option:
  Pin 34:
  1.8V: 7-bit = 0x37, 8-bit = 0x6E
  GND: 7-bit = 0x36, 8-bit = 0x6C
- MIPI Camera Datasheet: ARX3A0/D (page 21)
  www.onsemi.com
  TIMING SPECIFICATIONS
  Power−Up Sequence
  The recommended power−up sequence for ARX3A0 is
  showed in Figure 21. the available power supplies must
  have the separation specified below.
  1. Set XSHUTDOWN LOW.
  2. Power up VDD_IO (1.8 V only)
  3. After 1−500 ms, power up VDD, VDD_ANA,
  VDD_PLL VDD_PHY (1.2 V) and VAA,
  VAA_PIX (2.7 V) (any order).
  4. Apply EXTCLK (can be applied anytime).
  5. After 1−500 ms, set XSHUTDOWN.
  6. HOST configuration through I2C (PLL, output,
  etc).
  7. Set stream = 1 (R0x301A[2]).
  8. PLL internally enables and locks.
  9. ARX3A0 enters streaming mode.
- (near J12) "Standard" MIPI Camera

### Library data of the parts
C85-C87 C89 C91 = Cap_225M25VX5R0402_1: as C63 on sheet 7-CODEC
C88 C90 C92 C94 C96 = Cap: as C74 on sheet 7-CODEC
C93 C95 = Cap: as C73 on sheet 7-CODEC
J10 J12 = CONN_HIROSE_BM20_FPC_34PIN_0.4MM: Conn,FPC,34 pin,0.4mm pitch, 0,8mm height,SMT; Manufacturer 1: HiRose
J11 = Hdr_M_1X3_2M54_STRT_UNSHROUD: Hdr, 0.025" SQ Post Header, Through-hole, Vertical, -55 to 125 degC, 2.54 mm Pitch, 3-Pin, Male, RoHS; Manufacturer: Samtec; Manufacturer Part Number 1: TSW-103-07-L-S; Pitch: 2.54 mm
R69 R71 = Res3: Res,10K0,1%,100ppm,0402; Manufacturer 1: Stackpol; Manufacturer Part Number 1: RMCF0402FT10K0; Wattage: 63mW
R70 = Res3: Res,23K7,1%,100ppm,0402; Manufacturer 1: Stackpol; Manufacturer Part Number 1: RMCF0402FT23K7; Wattage: 63mW
R72 = Res3: as R60 on sheet 7-CODEC
R73 = Res3: Res,150K,1%,100ppm,0402; Manufacturer 1: Stackpol; Manufacturer Part Number 1: RMCF0402FT150K; Wattage: 63mW
R74 = Res3: as R62 on sheet 7-CODEC
R75 = Res3: DNI,Res,0R ohm,Jumper,0402; Manufacturer 1: Stackpol; Manufacturer Part Number 1: RMCF0402ZT0R00; Wattage: 63mW
SH11 = SHUNT_F_1x2_2.5MM_STRT: Shunt,Female,1x2,2.54mm,Gold,Strt; Manufacturer 1: Samtec; Manufacturer Part Number 1: SNT-100-BK-H
TP36-TP43 = TP_SMPAD: as TP26-TP29 on sheet 7-CODEC
U19 U20 = IC_LDO_NCV8164ASNADJT1G: as U12 on sheet 7-CODEC

## Sheet 10-MIPI_DSI.SchDoc: APP KIT BOARD
size 431 x 279 mm; Organization: ORGANIZATION; Address1: ADDRESS 1; Address2: ADDRESS 2; Address3: ADDRESS 3; Address4: ADDRESS 4; DocumentNumber: 10; Revision: -; SheetNumber: 10; SheetTotal: 14; ENG_APP_DATE: --/--/--; DSN_APP_DATE: --/--/--; CHK_APP_DATE: --/--/--
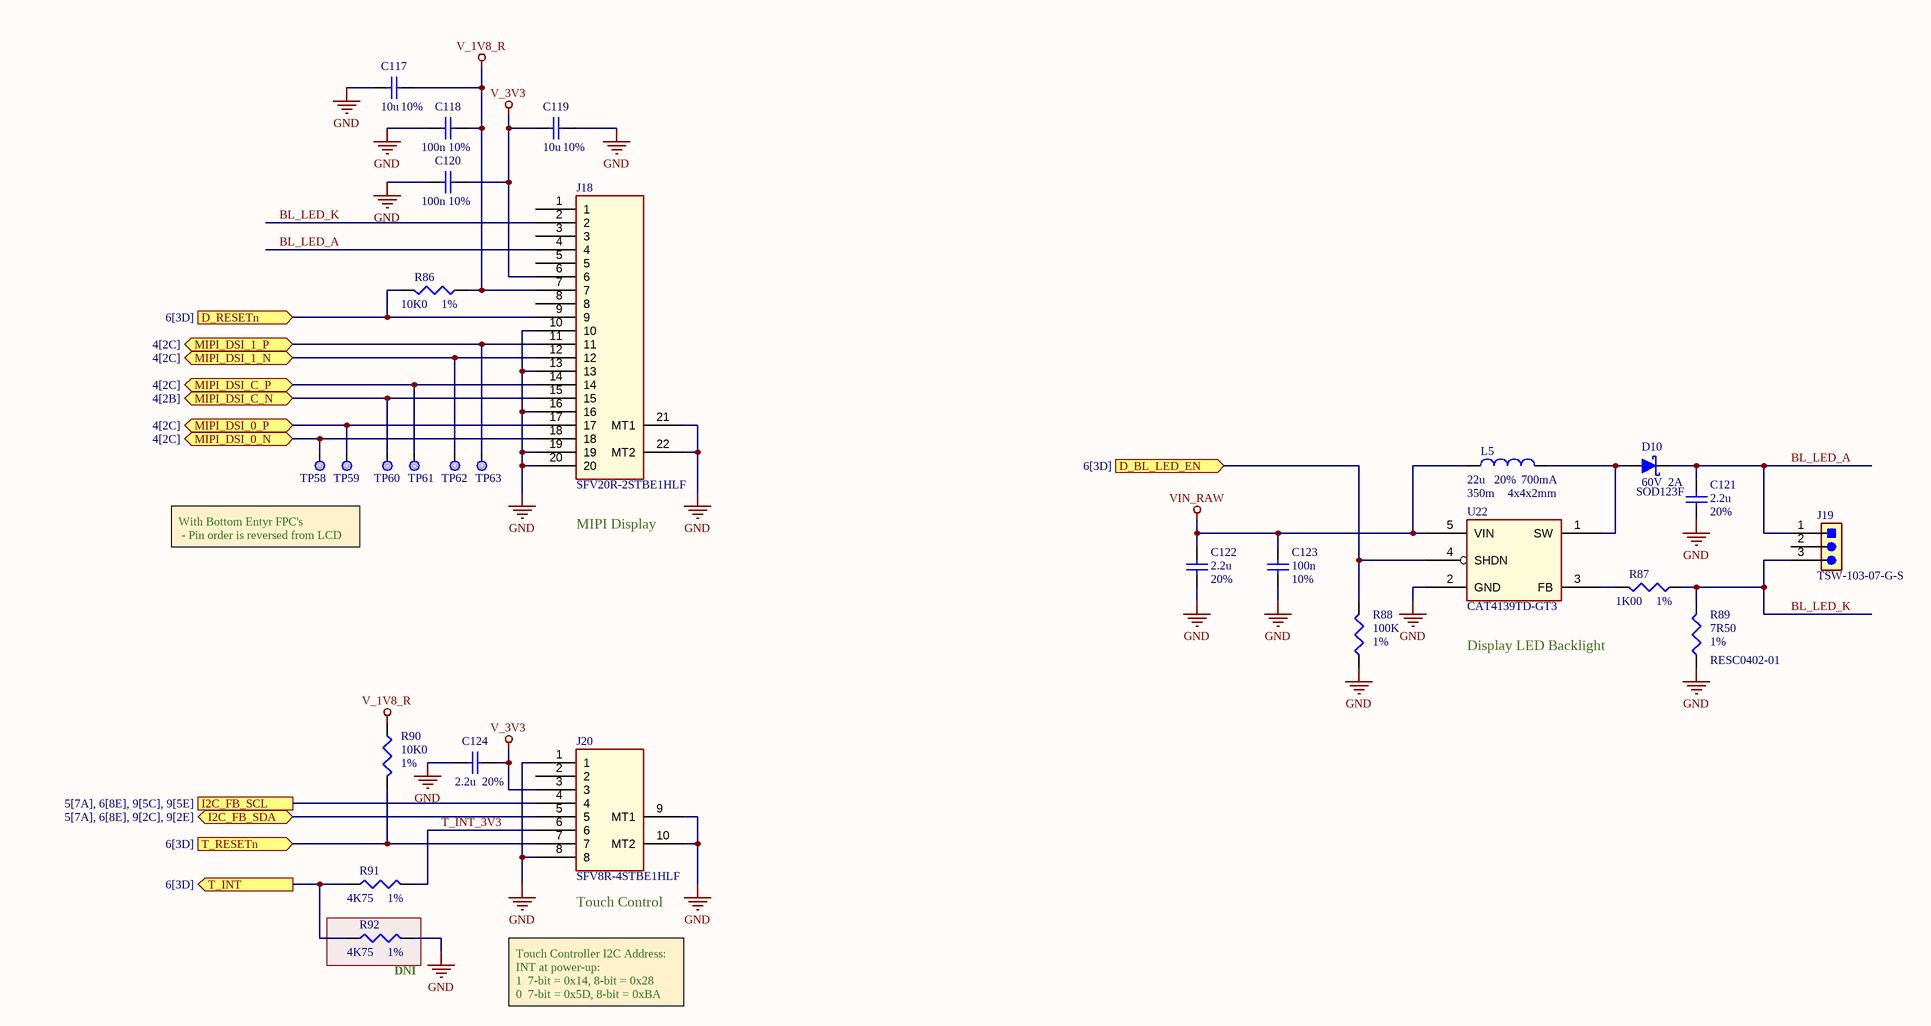
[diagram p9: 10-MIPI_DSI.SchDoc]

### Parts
C117  value 10u  Tolerance: 10%  [CAPC0402-01]  (hidden comment: Cap)
C118  value 100n  Tolerance: 10%  [CAPC0402-01]  (hidden comment: Cap)
C119  value 10u  Tolerance: 10%  [CAPC0402-01]  (hidden comment: Cap)
C120  value 100n  Tolerance: 10%  [CAPC0402-01]  (hidden comment: Cap)
C121  value 2.2u  Tolerance: 20%  [CAPC0402-01]  (hidden comment: Cap_225M25VX5R0402_1)
C122  value 2.2u  Tolerance: 20%  [CAPC0402-01]  (hidden comment: Cap_225M25VX5R0402_1)
C123  value 100n  Tolerance: 10%  [CAPC0402-01]  (hidden comment: Cap)
C124  value 2.2u  Tolerance: 20%  [CAPC0402-01]  (hidden comment: Cap_225M25VX5R0402_1)
D10  value 60V  2A  PackageDescription: SOD123F  [SOD123F_NXP]  (hidden comment: D Schottky)
J18  SFV20R-2STBE1HLF  [CONN_FPC_TOP-ENT_FRONT-SLIDE_0.50_20]
J19  TSW-103-07-G-S  [CONN_HDR_1X3_STRT_0.100]
J20  SFV8R-4STBE1HLF  [CONN_FPC_TOP-ENT_FRONT-SLIDE_0.50_8]
L5  value 22u  PackageDescription: 4x4x2mm  DCR: 350m  RMS_Current: 700mA  Tolerance: 20%  [IND_IFSC_1515AH_VIS-M]  (hidden comment: Inductor)
R86  value 10K0  Tolerance: 1%  [RESC0402-01]  (hidden comment: Res3)
R87  value 1K00  Tolerance: 1%  [RESC0402-01]  (hidden comment: Res3)
R88  value 100K  Tolerance: 1%  [RESC0402-01]  (hidden comment: Res3)
R89  value 7R50  Tolerance: 1%  [RESC0402-01]  (hidden comment: Res3)
R90  value 10K0  Tolerance: 1%  [RESC0402-01]  (hidden comment: Res3)
R91  value 4K75  Tolerance: 1%  [RESC0402-01]  (hidden comment: Res3)
R92  value 4K75  Tolerance: 1%  [RESC0402-01]  (hidden comment: Res3)
TP58  TP_SMPAD  [TP_30_RND]  (value not drawn)  (no BOM)
TP59  TP_SMPAD  [TP_30_RND]  (value not drawn)  (no BOM)
TP60  TP_SMPAD  [TP_30_RND]  (value not drawn)  (no BOM)
TP61  TP_SMPAD  [TP_30_RND]  (value not drawn)  (no BOM)
TP62  TP_SMPAD  [TP_30_RND]  (value not drawn)  (no BOM)
TP63  TP_SMPAD  [TP_30_RND]  (value not drawn)  (no BOM)
U22  CAT4139TD-GT3  [TSOT23-5_ONS]

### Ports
D_BL_LED_EN (in, see 6[3D]), D_RESETn (in, see 6[3D]), I2C_FB_SCL (see 5[7A], 6[8E], 9[5C], 9[5E]), I2C_FB_SDA (bidir, see 5[7A], 6[8E], 9[2C], 9[2E]), MIPI_DSI_0_N (bidir, see 4[2C]), MIPI_DSI_0_P (bidir, see 4[2C]), MIPI_DSI_1_N (bidir, see 4[2C]), MIPI_DSI_1_P (bidir, see 4[2C]), MIPI_DSI_C_N (bidir, see 4[2B]), MIPI_DSI_C_P (bidir, see 4[2C]), T_INT (out, see 6[3D]), T_RESETn (in, see 6[3D])

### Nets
GND: C117.2 C118.2 C119.1 C120.2 C121.1 C122.1 C123.2 C124.2 J18.10 J18.13 J18.16 J18.19 J18.20 J18.21(MT1) J18.22(MT2) J20.1 J20.8 J20.9(MT1) J20.10(MT2) R88.1 R89.1 R92.2 U22.2(GND)
V_1V8_R: C117.1 C118.1 J18.7 R86.1 R90.1
V_3V3: C119.2 C120.1 C124.1 J18.6 J20.3
VIN_RAW: C122.2 C123.1 L5.1 U22.5(VIN)
BL_LED_A: C121.2 D10.1(K) J18.4 J19.1
BL_LED_K: J18.2 J19.3 R87.1 R89.2
D_RESETn: J18.9 R86.2 ; port D_RESETn
I2C_FB_SCL: J20.4 ; port I2C_FB_SCL
I2C_FB_SDA: J20.5 ; port I2C_FB_SDA
MIPI_DSI_0_N: J18.18 TP58.1 ; port MIPI_DSI_0_N
MIPI_DSI_0_P: J18.17 TP59.1 ; port MIPI_DSI_0_P
MIPI_DSI_1_N: J18.12 TP62.1 ; port MIPI_DSI_1_N
MIPI_DSI_1_P: J18.11 TP63.1 ; port MIPI_DSI_1_P
MIPI_DSI_C_N: J18.15 TP60.1 ; port MIPI_DSI_C_N
MIPI_DSI_C_P: J18.14 TP61.1 ; port MIPI_DSI_C_P
P4_0: J20.7 R90.2 ; port T_RESETn
P6_1: R88.2 U22.4(SHDN) ; port D_BL_LED_EN
P9_4: R91.1 R92.1 ; port T_INT
T_INT_3V3: J20.6 R91.2
NetD10_2: D10.2(A) L5.2 U22.1(SW)
NetR87_2: R87.2 U22.3(FB)

Not connected (* = marked no-connect by the designer): J18 1 3 5 8; J19 2; J20 2

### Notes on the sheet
- With Bottom Entyr FPC's
  - Pin order is reversed from LCD
- (near J18) MIPI Display
- Display LED Backlight
- (near J20) Touch Control
- (near R92) DNI
- Touch Controller I2C Address:
  INT at power-up:
  1  7-bit = 0x14, 8-bit = 0x28
  0  7-bit = 0x5D, 8-bit = 0xBA

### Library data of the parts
C117 C119 = Cap: as C74 on sheet 7-CODEC
C118 C120 C123 = Cap: as C57-C59 on sheet 7-CODEC
C121 C122 C124 = Cap_225M25VX5R0402_1: as C63 on sheet 7-CODEC
D10 = D Schottky: Diode,Schottky,2A,60V, <50uA@60V,SOD123F; Manufacturer 1: OnSemi; Manufacturer Part Number 1: SS26FL
J18 = Conn_FFC_TOP_SLIDEorLOCK_0.50_20pin: Conn,FlatFlex,20 pin,0.50mm,top-entry,slide-flap,SMT; Manufacturer 1: Amphenol
J19 = Hdr_M_1X3_2M54_STRT_UNSHROUD: as J11 on sheet 9-MIPI_CSI
J20 = Conn_FFC_TOP_SLIDorLOCK_0.50_8pin: Conn,FlatFlex,8 pin,0.50mm,top-entry,slide-flap,SMT; Mfr_Name: Omron; Manufacturer 1: Amphenol
L5 = Inductor: Ind,Shielded,22uH,20%,700mA,350mOhm,4x4x2mm; Manufacturer 1: Vishay; Manufacturer Part Number 1: IFSC1515AHER220M0; PCB_Footprint: LC0402
R86 R90 = Res3: as R69 on sheet 9-MIPI_CSI
R87 = Res3: Res,1K00,1%,100ppm,0402; Manufacturer 1: Stackpol; Manufacturer Part Number 1: RMCF0402FT1K; Wattage: 63mW
R88 = Res3: as R60 on sheet 7-CODEC
R89 = Res3: Res,7R50,1%,100ppm,0402; Manufacturer 1: Stackpol; Manufacturer Part Number 1: RMCF0402FT7R5; Wattage: 63mW
R91 = Res3: Res,4K75,1%,100ppm,0402; Manufacturer 1: Stackpol; Manufacturer Part Number 1: RMCF0402FT4K75; Wattage: 63mW
R92 = Res3: DNI,Res,4K75,1%,100ppm,0402; Manufacturer 1: Stackpol; Manufacturer Part Number 1: RMCF0402FT4K75; Wattage: 63mW
TP58-TP63 = TP_SMPAD: as TP26-TP29 on sheet 7-CODEC
U22 = IC_BOOST_CAT4139TD-GT3: IC, Boost Converter, LED Driver; Manufacturer 1: OnSemi

## Sheet 11-CPU_GPIO.SchDoc: APP KIT BOARD
size 431 x 279 mm; Organization: ORGANIZATION; Address1: ADDRESS 1; Address2: ADDRESS 2; Address3: ADDRESS 3; Address4: ADDRESS 4; DocumentNumber: 11; Revision: -; SheetNumber: 11; SheetTotal: 14; ENG_APP_DATE: --/--/--; DSN_APP_DATE: --/--/--; CHK_APP_DATE: --/--/--
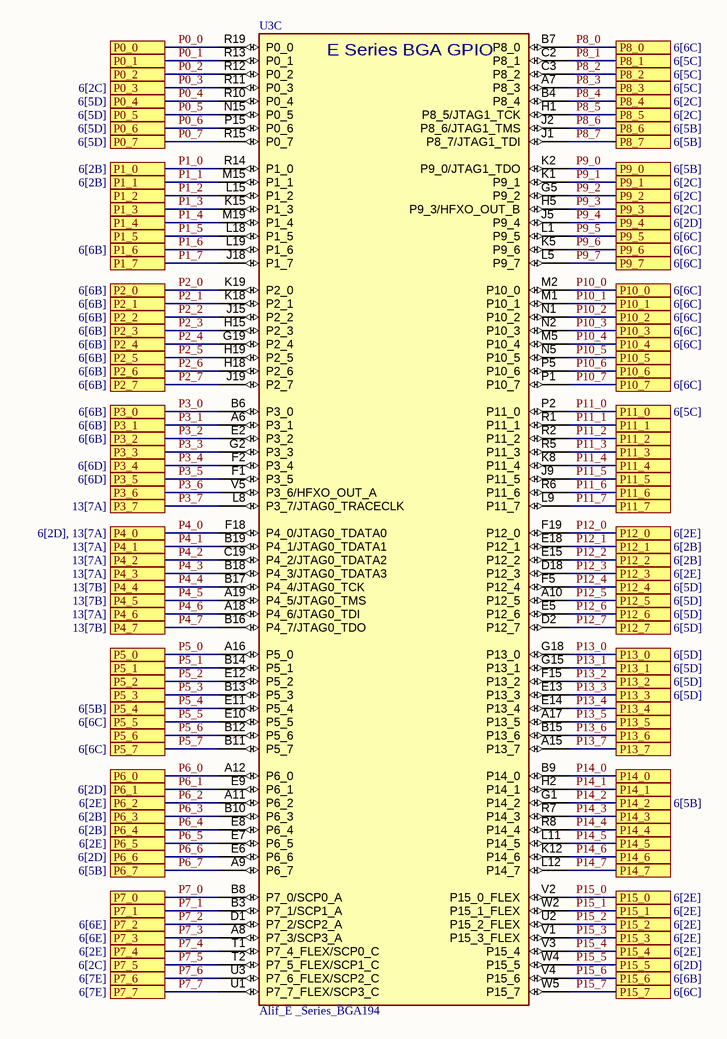
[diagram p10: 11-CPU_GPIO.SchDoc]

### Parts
U3  Alif_E _Series_BGA194  [BGA194 _CENTERED]  (part C of 4)

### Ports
P0_0, P0_1, P0_2, P0_3 (see 6[2C]), P0_4 (see 6[5D]), P0_5 (see 6[5D]), P0_6 (see 6[5D]), P0_7 (see 6[5D]), P1_0 (see 6[2B]), P1_1 (see 6[2B]), P1_2, P1_3, P1_4, P1_5, P1_6 (see 6[6B]), P1_7, P2_0 (see 6[6B]), P2_1 (see 6[6B]), P2_2 (see 6[6B]), P2_3 (see 6[6B]), P2_4 (see 6[6B]), P2_5 (see 6[6B]), P2_6 (see 6[6B]), P2_7 (see 6[6B]), P3_0 (see 6[6B]), P3_1 (see 6[6B]), P3_2 (see 6[6B]), P3_3, P3_4 (see 6[6D]), P3_5 (see 6[6D]), P3_6, P3_7 (see 13[7A]), P4_0 (see 6[2D], 13[7A]), P4_1 (see 13[7A]), P4_2 (see 13[7A]), P4_3 (see 13[7A]), P4_4 (see 13[7B]), P4_5 (see 13[7B]), P4_6 (see 13[7A]), P4_7 (see 13[7B]), P5_0, P5_1, P5_2, P5_3, P5_4 (see 6[5B]), P5_5 (see 6[6C]), P5_6, P5_7 (see 6[6C]), P6_0, P6_1 (see 6[2D]), P6_2 (see 6[2E]), P6_3 (see 6[2B]), P6_4 (see 6[2B]), P6_5 (see 6[2E]), P6_6 (see 6[2D]), P6_7 (see 6[5B]), P7_0, P7_1, P7_2 (see 6[6E]), P7_3 (see 6[6E]), P7_4 (see 6[2E]), P7_5 (see 6[2C]), P7_6 (see 6[7E]), P7_7 (see 6[7E]), P8_0 (see 6[6C]), P8_1 (see 6[5C]), P8_2 (see 6[5C]), P8_3 (see 6[5C]), P8_4 (see 6[2C]), P8_5 (see 6[2C]), P8_6 (see 6[5B]), P8_7 (see 6[5B]), P9_0 (see 6[5B]), P9_1 (see 6[2C]), P9_2 (see 6[2C]), P9_3 (see 6[2C]), P9_4 (see 6[2D]), P9_5 (see 6[6C]), P9_6 (see 6[6C]), P9_7 (see 6[6C]), P10_0 (see 6[6C]), P10_1 (see 6[6C]), P10_2 (see 6[6C]), P10_3 (see 6[6C]), P10_4 (see 6[6C]), P10_5, P10_6, P10_7 (see 6[6C]), P11_0 (see 6[5C]), P11_1, P11_2, P11_3, P11_4, P11_5, P11_6, P11_7, P12_0 (see 6[2E]), P12_1 (see 6[2B]), P12_2 (see 6[2B]), P12_3 (see 6[2E]), P12_4 (see 6[5D]), P12_5 (see 6[5D]), P12_6 (see 6[5D]), P12_7 (see 6[5D]), P13_0 (see 6[5D]), P13_1 (see 6[5D]), P13_2 (see 6[5D]), P13_3 (see 6[5D]), P13_4, P13_5, P13_6, P13_7, P14_0, P14_1, P14_2 (see 6[5B]), P14_3, P14_4, P14_5, P14_6, P14_7, P15_0 (see 6[2E]), P15_1 (see 6[2E]), P15_2 (see 6[2E]), P15_3 (see 6[2E]), P15_4 (see 6[2E]), P15_5 (see 6[2D]), P15_6 (see 6[6B]), P15_7 (see 6[6C])

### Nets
P0_0: U3.R19(P0_0) ; port P0_0
P0_1: U3.R13(P0_1) ; port P0_1
P0_2: U3.R12(P0_2) ; port P0_2
P0_3: U3.R11(P0_3) ; port P0_3
P0_4: U3.R10(P0_4) ; port P0_4
P0_5: U3.N15(P0_5) ; port P0_5
P0_6: U3.P15(P0_6) ; port P0_6
P0_7: U3.R15(P0_7) ; port P0_7
P1_0: U3.R14(P1_0) ; port P1_0
P1_1: U3.M15(P1_1) ; port P1_1
P1_2: U3.L15(P1_2) ; port P1_2
P1_3: U3.K15(P1_3) ; port P1_3
P1_4: U3.M19(P1_4) ; port P1_4
P1_5: U3.L18(P1_5) ; port P1_5
P1_6: U3.L19(P1_6) ; port P1_6  [project net OSPI0_RXDS]
P1_7: U3.J18(P1_7) ; port P1_7
P2_0: U3.K19(P2_0) ; port P2_0  [project net OSPI0_D0]
P2_1: U3.K18(P2_1) ; port P2_1  [project net OSPI0_D1]
P2_2: U3.J15(P2_2) ; port P2_2  [project net OSPI0_D2]
P2_3: U3.H15(P2_3) ; port P2_3  [project net OSPI0_D3]
P2_4: U3.G19(P2_4) ; port P2_4  [project net OSPI0_D4]
P2_5: U3.H19(P2_5) ; port P2_5  [project net OSPI0_D5]
P2_6: U3.H18(P2_6) ; port P2_6  [project net OSPI0_D6]
P2_7: U3.J19(P2_7) ; port P2_7  [project net OSPI0_D7]
P3_0: U3.B6(P3_0) ; port P3_0  [project net OSPI0_SCLK]
P3_1: U3.A6(P3_1) ; port P3_1  [project net OSPI0_SCLKN]
P3_2: U3.E2(P3_2) ; port P3_2
P3_3: U3.G2(P3_3) ; port P3_3
P3_4: U3.F2(P3_4) ; port P3_4  [project net I2C_CL_SCL]
P3_5: U3.F1(P3_5) ; port P3_5  [project net I2C_CL_SDA]
P3_6: U3.V5(P3_6/HFXO_OUT_A) ; port P3_6
P3_7: U3.L8(P3_7/JTAG0_TRACECLK) ; port P3_7
P4_0: U3.F18(P4_0/JTAG0_TDATA0) ; port P4_0
P4_1: U3.B19(P4_1/JTAG0_TDATA1) ; port P4_1
P4_2: U3.C19(P4_2/JTAG0_TDATA2) ; port P4_2
P4_3: U3.B18(P4_3/JTAG0_TDATA3) ; port P4_3
P4_4: U3.B17(P4_4/JTAG0_TCK) ; port P4_4
P4_5: U3.A19(P4_5/JTAG0_TMS) ; port P4_5
P4_6: U3.A18(P4_6/JTAG0_TDI) ; port P4_6
P4_7: U3.B16(P4_7/JTAG0_TDO) ; port P4_7
P5_0: U3.A16(P5_0) ; port P5_0
P5_1: U3.B14(P5_1) ; port P5_1
P5_2: U3.E12(P5_2) ; port P5_2
P5_3: U3.B13(P5_3) ; port P5_3
P5_4: U3.E11(P5_4) ; port P5_4
P5_5: U3.E10(P5_5) ; port P5_5  [project net OSPI1_SCLK]
P5_6: U3.B12(P5_6) ; port P5_6
P5_7: U3.B11(P5_7) ; port P5_7
P6_0: U3.A12(P6_0) ; port P6_0
P6_1: U3.E9(P6_1) ; port P6_1
P6_2: U3.A11(P6_2) ; port P6_2
P6_3: U3.B10(P6_3) ; port P6_3
P6_4: U3.E8(P6_4) ; port P6_4
P6_5: U3.E7(P6_5) ; port P6_5
P6_6: U3.E6(P6_6) ; port P6_6
P6_7: U3.A9(P6_7) ; port P6_7
P7_0: U3.B8(P7_0/SCP0_A) ; port P7_0
P7_1: U3.B3(P7_1/SCP1_A) ; port P7_1
P7_2: U3.D1(P7_2/SCP2_A) ; port P7_2  [project net I2C_FB_SDA]
P7_3: U3.A8(P7_3/SCP3_A) ; port P7_3  [project net I2C_FB_SCL]
P7_4: U3.T1(P7_4_FLEX/SCP0_C) ; port P7_4
P7_5: U3.T2(P7_5_FLEX/SCP1_C) ; port P7_5  [project net C_EN_MIPI_PWR]
P7_6: U3.U3(P7_6_FLEX/SCP2_C) ; port P7_6  [project net I3C_SDA]
P7_7: U3.U1(P7_7_FLEX/SCP3_C) ; port P7_7  [project net I3C_SCL]
P8_0: U3.B7(P8_0) ; port P8_0  [project net OSPI1_SCLKN]
P8_1: U3.C2(P8_1) ; port P8_1
P8_2: U3.C3(P8_2) ; port P8_2
P8_3: U3.A7(P8_3) ; port P8_3
P8_4: U3.B4(P8_4) ; port P8_4
P8_5: U3.H1(P8_5/JTAG1_TCK) ; port P8_5
P8_6: U3.J2(P8_6/JTAG1_TMS) ; port P8_6
P8_7: U3.J1(P8_7/JTAG1_TDI) ; port P8_7
P9_0: U3.K2(P9_0/JTAG1_TDO) ; port P9_0
P9_1: U3.K1(P9_1) ; port P9_1  [project net C_RESETn]
P9_2: U3.G5(P9_2) ; port P9_2
P9_3: U3.H5(P9_3/HFXO_OUT_B) ; port P9_3
P9_4: U3.J5(P9_4) ; port P9_4
P9_5: U3.L1(P9_5) ; port P9_5  [project net OSPI1_D0]
P9_6: U3.K5(P9_6) ; port P9_6  [project net OSPI1_D1]
P9_7: U3.L5(P9_7) ; port P9_7  [project net OSPI1_D2]
P10_0: U3.M2(P10_0) ; port P10_0  [project net OSPI1_D3]
P10_1: U3.M1(P10_1) ; port P10_1  [project net OSPI1_D4]
P10_2: U3.N1(P10_2) ; port P10_2  [project net OSPI1_D5]
P10_3: U3.N2(P10_3) ; port P10_3  [project net OSPI1_D6]
P10_4: U3.M5(P10_4) ; port P10_4  [project net OSPI1_D7]
P10_5: U3.N5(P10_5) ; port P10_5
P10_6: U3.P5(P10_6) ; port P10_6
P10_7: U3.P1(P10_7) ; port P10_7  [project net OSPI1_RXDS]
P11_0: U3.P2(P11_0) ; port P11_0
P11_1: U3.R1(P11_1) ; port P11_1
P11_2: U3.R2(P11_2) ; port P11_2
P11_3: U3.R5(P11_3) ; port P11_3
P11_4: U3.K8(P11_4) ; port P11_4
P11_5: U3.J9(P11_5) ; port P11_5
P11_6: U3.R6(P11_6) ; port P11_6
P11_7: U3.L9(P11_7) ; port P11_7
P12_0: U3.F19(P12_0) ; port P12_0
P12_1: U3.E18(P12_1) ; port P12_1
P12_2: U3.E15(P12_2) ; port P12_2
P12_3: U3.D18(P12_3) ; port P12_3
P12_4: U3.F5(P12_4) ; port P12_4
P12_5: U3.A10(P12_5) ; port P12_5
P12_6: U3.E5(P12_6) ; port P12_6
P12_7: U3.D2(P12_7) ; port P12_7
P13_0: U3.G18(P13_0) ; port P13_0
P13_1: U3.G15(P13_1) ; port P13_1
P13_2: U3.F15(P13_2) ; port P13_2
P13_3: U3.E13(P13_3) ; port P13_3
P13_4: U3.E14(P13_4) ; port P13_4
P13_5: U3.A17(P13_5) ; port P13_5
P13_6: U3.B15(P13_6) ; port P13_6
P13_7: U3.A15(P13_7) ; port P13_7
P14_0: U3.B9(P14_0) ; port P14_0
P14_1: U3.H2(P14_1) ; port P14_1
P14_2: U3.G1(P14_2) ; port P14_2
P14_3: U3.R7(P14_3) ; port P14_3
P14_4: U3.R8(P14_4) ; port P14_4
P14_5: U3.L11(P14_5) ; port P14_5
P14_6: U3.K12(P14_6) ; port P14_6
P14_7: U3.L12(P14_7) ; port P14_7
P15_0: U3.V2(P15_0_FLEX) ; port P15_0
P15_1: U3.W2(P15_1_FLEX) ; port P15_1
P15_2: U3.U2(P15_2_FLEX) ; port P15_2
P15_3: U3.V1(P15_3_FLEX) ; port P15_3
P15_4: U3.V3(P15_4) ; port P15_4
P15_5: U3.W4(P15_5) ; port P15_5  [project net D_RESETn]
P15_6: U3.V4(P15_6) ; port P15_6  [project net OSPI0_RESETn]
P15_7: U3.W5(P15_7) ; port P15_7  [project net OSPI1_RESETn]

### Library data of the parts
U3 = E7_B0_194BGA: IC,Alif E7 MCU, Rev B silicon,BGA194; Manufacturer 1: Alif Semi; Manufacturer Part Number 1: AE722F80F55D5LS

## Sheet 12-JLINK_1.SchDoc: APP KIT BOARD
size 431 x 279 mm; Organization: ORGANIZATION; Address1: ADDRESS 1; Address2: ADDRESS 2; Address3: ADDRESS 3; Address4: ADDRESS 4; DocumentNumber: 12; Revision: -; SheetNumber: 12; SheetTotal: 14; ENG_APP_DATE: --/--/--; DSN_APP_DATE: --/--/--; CHK_APP_DATE: --/--/--
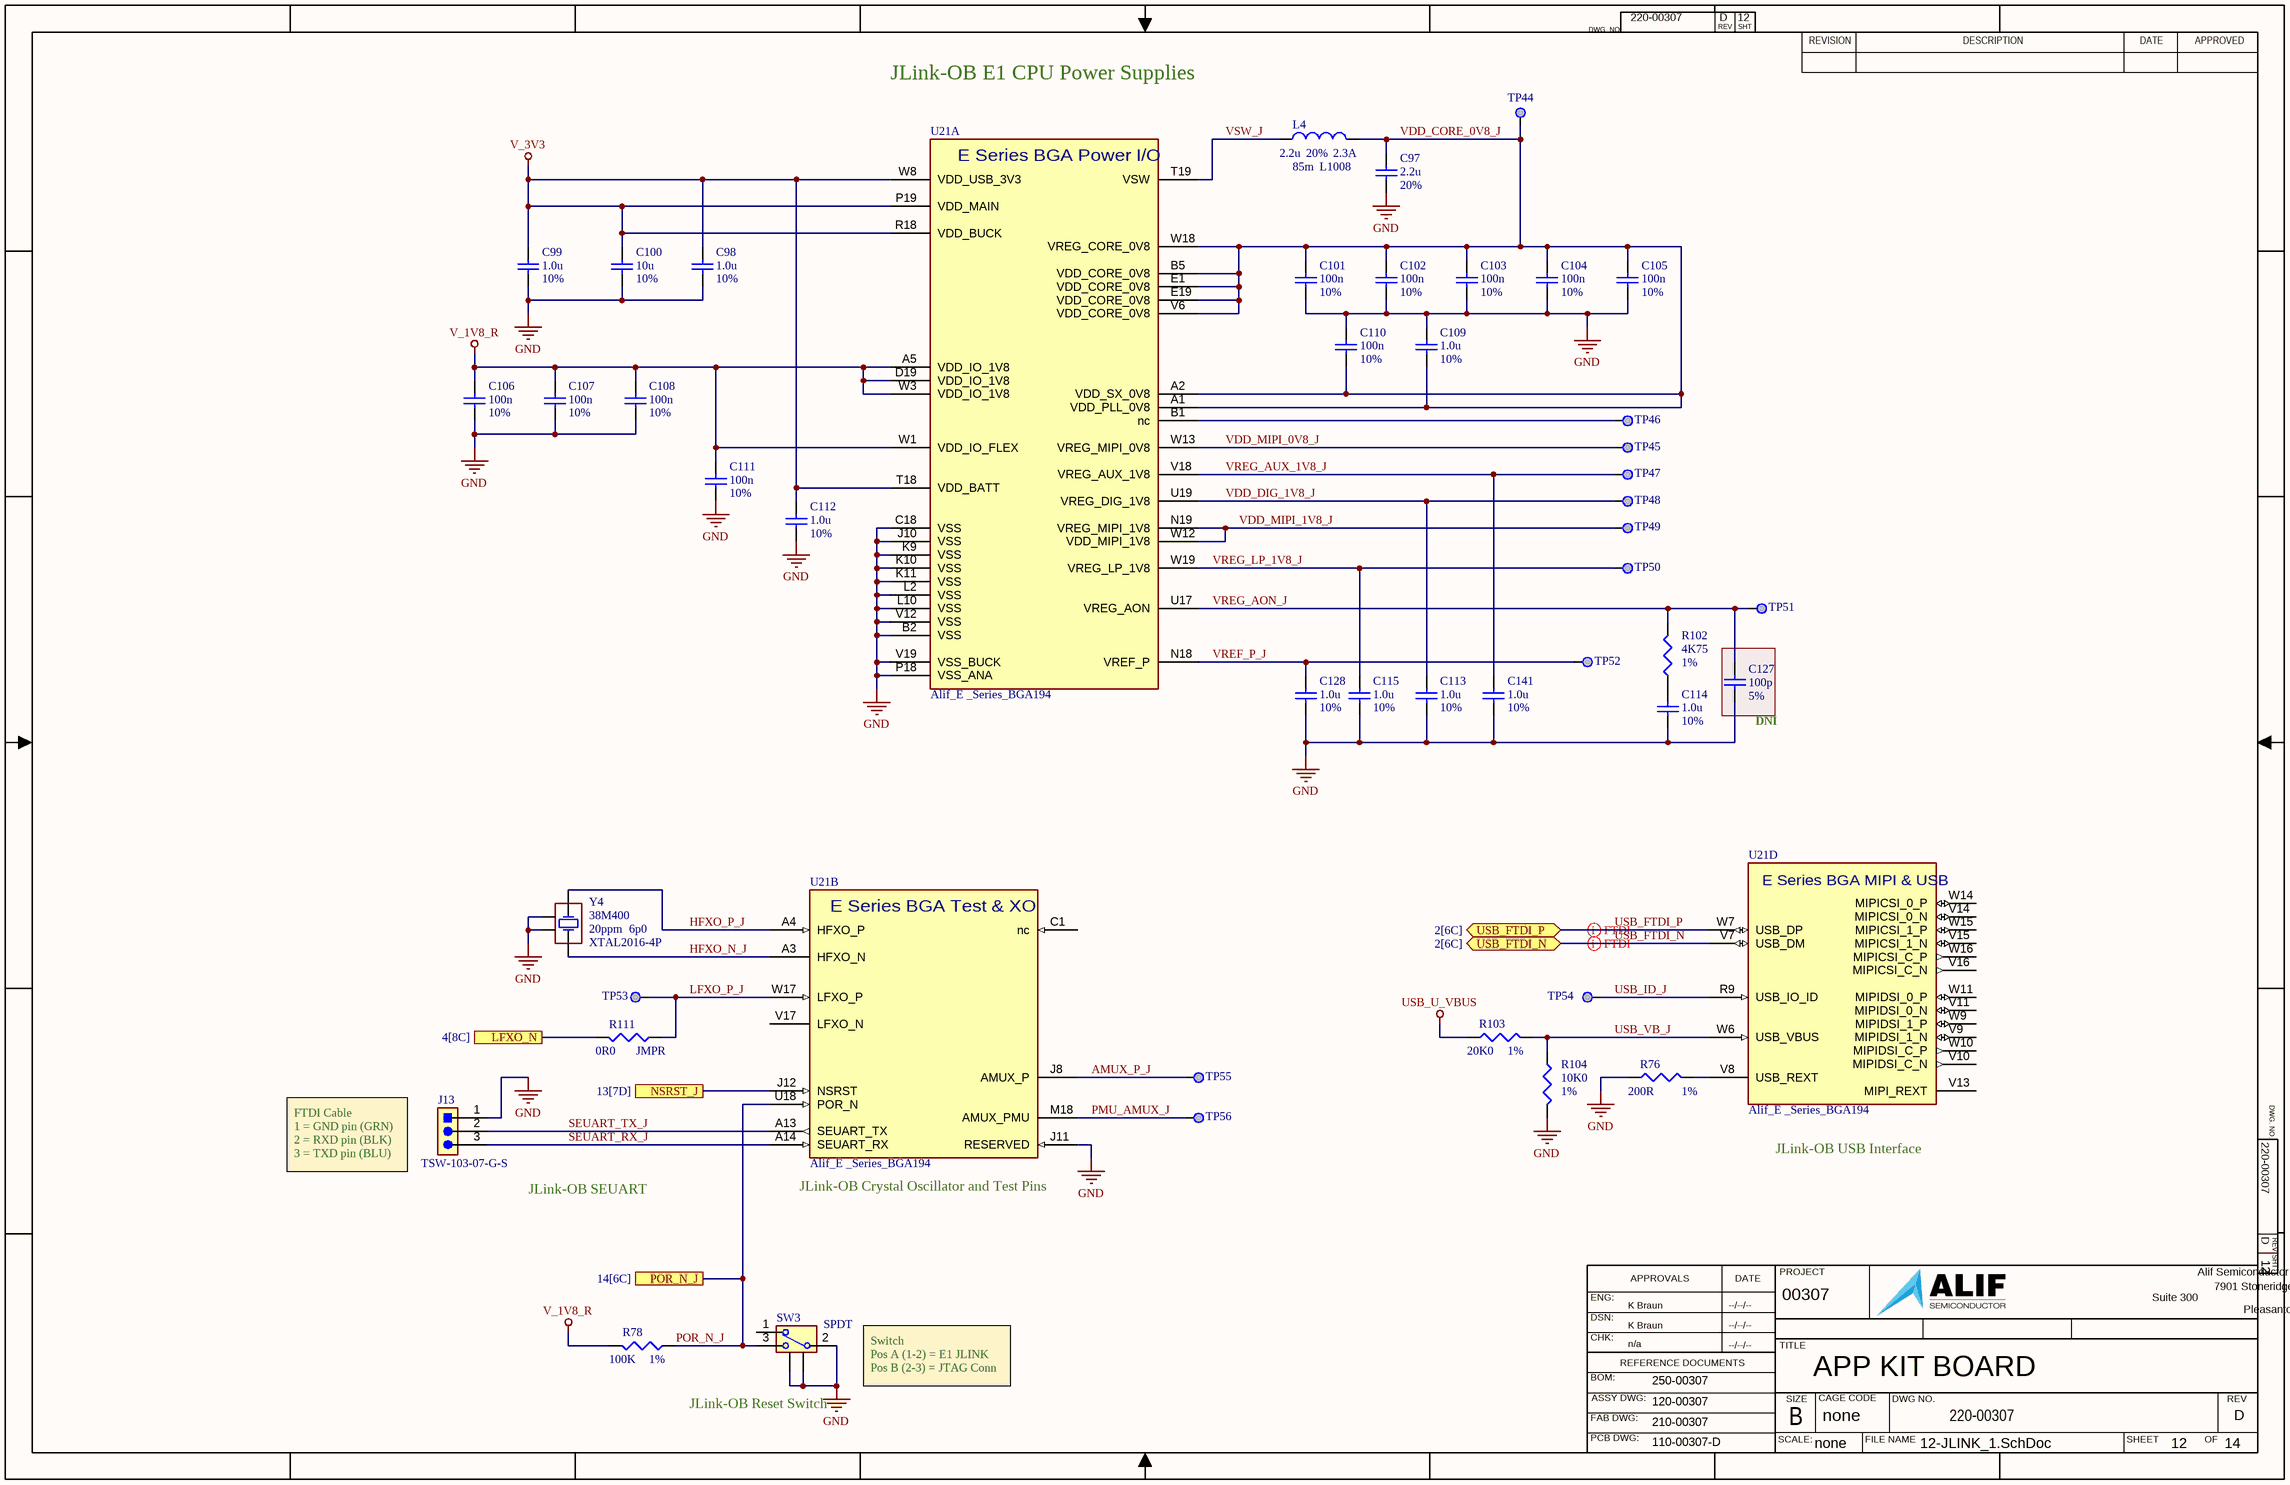
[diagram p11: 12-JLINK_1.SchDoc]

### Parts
C97  value 2.2u  Tolerance: 20%  [CAPC0402-01]  (hidden comment: Cap_225M25VX5R0402_1)
C98  value 1.0u  Tolerance: 10%  [CAPC0402-01]  (hidden comment: Cap)
C99  value 1.0u  Tolerance: 10%  [CAPC0402-01]  (hidden comment: Cap)
C100  value 10u  Tolerance: 10%  [CAPC0402-01]  (hidden comment: Cap)
C101  value 100n  Tolerance: 10%  [CAPC0402-01]  (hidden comment: Cap)
C102  value 100n  Tolerance: 10%  [CAPC0402-01]  (hidden comment: Cap)
C103  value 100n  Tolerance: 10%  [CAPC0402-01]  (hidden comment: Cap)
C104  value 100n  Tolerance: 10%  [CAPC0402-01]  (hidden comment: Cap)
C105  value 100n  Tolerance: 10%  [CAPC0402-01]  (hidden comment: Cap)
C106  value 100n  Tolerance: 10%  [CAPC0402-01]  (hidden comment: Cap)
C107  value 100n  Tolerance: 10%  [CAPC0402-01]  (hidden comment: Cap)
C108  value 100n  Tolerance: 10%  [CAPC0402-01]  (hidden comment: Cap)
C109  value 1.0u  Tolerance: 10%  [CAPC0402-01]  (hidden comment: Cap)
C110  value 100n  Tolerance: 10%  [CAPC0402-01]  (hidden comment: Cap)
C111  value 100n  Tolerance: 10%  [CAPC0402-01]  (hidden comment: Cap)
C112  value 1.0u  Tolerance: 10%  [CAPC0402-01]  (hidden comment: Cap)
C113  value 1.0u  Tolerance: 10%  [CAPC0402-01]  (hidden comment: Cap)
C114  value 1.0u  Tolerance: 10%  [CAPC0402-01]  (hidden comment: Cap)
C115  value 1.0u  Tolerance: 10%  [CAPC0402-01]  (hidden comment: Cap)
C127  value 100p  Tolerance: 5%  [CAPC0402-01]  (hidden comment: Cap)
C128  value 1.0u  Tolerance: 10%  [CAPC0402-01]  (hidden comment: Cap)
C141  value 1.0u  Tolerance: 10%  [CAPC0402-01]  (hidden comment: Cap)
J13  TSW-103-07-G-S  [CONN_HDR_1X3_STRT_0.100]
L4  value 2.2u  PackageReference: L1008  DCR: 85m  RMS_Current: 2.3A  Tolerance: 20%  [INDC2520X120N]  (hidden comment: Inductor)
R76  value 200R  Tolerance: 1%  [RESC0402-01]  (hidden comment: Res3)
R78  value 100K  Tolerance: 1%  [RESC0402-01]  (hidden comment: Res3)
R102  value 4K75  Tolerance: 1%  [RESC0402-01]  (hidden comment: Res3)
R103  value 20K0  Tolerance: 1%  [RESC0402-01]  (hidden comment: Res3)
R104  value 10K0  Tolerance: 1%  [RESC0402-01]  (hidden comment: Res3)
R111  value 0R0  Tolerance: JMPR  [RESC0402-01]  (hidden comment: Res3)
SW3  SPDT  [SW_SPDT_OS10201MSQN1]
TP44  TP_SMPAD  [TP_30_RND]  (value not drawn)  (no BOM)
TP45  TP_SMPAD  [TP_30_RND]  (value not drawn)  (no BOM)
TP46  TP_SMPAD  [TP_30_RND]  (value not drawn)  (no BOM)
TP47  TP_SMPAD  [TP_30_RND]  (value not drawn)  (no BOM)
TP48  TP_SMPAD  [TP_30_RND]  (value not drawn)  (no BOM)
TP49  TP_SMPAD  [TP_30_RND]  (value not drawn)  (no BOM)
TP50  TP_SMPAD  [TP_30_RND]  (value not drawn)  (no BOM)
TP51  TP_SMPAD  [TP_30_RND]  (value not drawn)  (no BOM)
TP52  TP_SMPAD  [TP_30_RND]  (value not drawn)  (no BOM)
TP53  TP_SMPAD  [TP_30_RND]  (value not drawn)  (no BOM)
TP54  TP_SMPAD  [TP_30_RND]  (value not drawn)  (no BOM)
TP55  TP_SMPAD  [TP_30_RND]  (value not drawn)  (no BOM)
TP56  TP_SMPAD  [TP_30_RND]  (value not drawn)  (no BOM)
U21  Alif_E _Series_BGA194  [BGA194 _CENTERED]  (parts A,B,D of 4)
Y4  value 38M400  PCB_Footprint: XTAL2016-4P  PPM: 20ppm  Load Cap: 6p0  [OSC_4p_2016_XRCGB38M400F2P00R0]  (hidden comment: Xtal_38M4_20PPM6PF_2016-4P_1)

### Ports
LFXO_N (see 4[8C]), NSRST_J (see 13[7D]), POR_N_J (see 14[6C]), USB_FTDI_N (bidir, see 2[6C]), USB_FTDI_P (bidir, see 2[6C])

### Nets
GND: C97.1 C98.1 C99.1 C100.1 C101.1 C102.1 C103.1 C104.1 C105.1 C106.1 C107.1 C108.1 C109.2 C110.2 C111.1 C112.1 C113.1 C114.1 C115.1 C127.1 C128.1 C141.1 J13.1 R76.1 R104.2 SW3.2(COMMON) SW3.4(G1) SW3.5(G2) U21.B2(VSS) U21.C18(VSS) U21.J10(VSS) U21.J11(RESERVED) U21.K9(VSS) U21.K10(VSS) U21.K11(VSS) U21.L2(VSS) U21.L10(VSS) U21.P18(VSS_ANA) U21.V12(VSS) U21.V19(VSS_BUCK) Y4.2 Y4.4
USB_U_VBUS: R103.1
V_1V8_R: C106.2 C107.2 C108.2 C111.2 R78.2 U21.A5(VDD_IO_1V8) U21.D19(VDD_IO_1V8) U21.W1(VDD_IO_FLEX) U21.W3(VDD_IO_1V8)
V_3V3: C98.2 C99.2 C100.2 C112.2 U21.P19(VDD_MAIN) U21.R18(VDD_BUCK) U21.T18(VDD_BATT) U21.W8(VDD_USB_3V3)
AMUX_P_J: TP55.1 U21.J8(AMUX_P)
HFXO_N_J: U21.A3(HFXO_N) Y4.3(OSC2)
HFXO_P_J: U21.A4(HFXO_P) Y4.1(OSC1)
LFXO_N: R111.2 ; port LFXO_N
LFXO_P_J: R111.1 TP53.1 U21.W17(LFXO_P)
NSRST_J: U21.J12(NSRST) ; port NSRST_J
PMU_AMUX_J: TP56.1 U21.M18(AMUX_PMU)
POR_N_J: R78.1 SW3.3(NO) U21.U18(POR_N) ; port POR_N_J
SEUART_RX_J: J13.3 U21.A14(SEUART_RX)
SEUART_TX_J: J13.2 U21.A13(SEUART_TX)
USB_FTDI_N: U21.V7(USB_DM) ; port USB_FTDI_N
USB_FTDI_P: U21.W7(USB_DP) ; port USB_FTDI_P
USB_ID_J: TP54.1 U21.R9(USB_IO_ID)
USB_VB_J: R103.2 R104.1 U21.W6(USB_VBUS)
VDD_CORE_0V8_J: C97.2 C101.2 C102.2 C103.2 C104.2 C105.2 C109.1 C110.1 L4.2 TP44.1 U21.A1(VDD_PLL_0V8) U21.A2(VDD_SX_0V8) U21.B5(VDD_CORE_0V8) U21.E1(VDD_CORE_0V8) U21.E19(VDD_CORE_0V8) U21.V6(VDD_CORE_0V8) U21.W18(VREG_CORE_0V8)
VDD_DIG_1V8_J: C113.2 TP48.1 U21.U19(VREG_DIG_1V8)
VDD_MIPI_0V8_J: TP45.1 U21.W13(VREG_MIPI_0V8)
VDD_MIPI_1V8_J: TP49.1 U21.N19(VREG_MIPI_1V8) U21.W12(VDD_MIPI_1V8)
VREF_P_J: C128.2 TP52.1 U21.N18(VREF_P)
VREG_AON_J: C127.2 R102.2 TP51.1 U21.U17(VREG_AON)
VREG_AUX_1V8_J: C141.2 TP47.1 U21.V18(VREG_AUX_1V8)
VREG_LP_1V8_J: C115.2 TP50.1 U21.W19(VREG_LP_1V8)
VSW_J: L4.1 U21.T19(VSW)
NetC114_2: C114.2 R102.1
NetR76_2: R76.2 U21.V8(USB_REXT)
NetTP46_1: TP46.1 U21.B1(nc)

Not connected (* = marked no-connect by the designer): SW3 1(NC); U21 C1(nc) V9(MIPIDSI_1_N) V10(MIPIDSI_C_N) V11(MIPIDSI_0_N) V13(MIPI_REXT) V14(MIPICSI_0_N) V15(MIPICSI_1_N) V16(MIPICSI_C_N) V17(LFXO_N) W9(MIPIDSI_1_P) W10(MIPIDSI_C_P) W11(MIPIDSI_0_P) W14(MIPICSI_0_P) W15(MIPICSI_1_P) W16(MIPICSI_C_P)

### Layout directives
differential pair; differential pair class USB_FTDI: USB_FTDI_N, USB_FTDI_P

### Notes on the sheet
- JLink-OB E1 CPU Power Supplies
- (near C127) DNI
- FTDI Cable
  1 = GND pin (GRN)
  2 = RXD pin (BLK)
  3 = TXD pin (BLU)
- (near U21) JLink-OB USB Interface
- (near J13) JLink-OB SEUART
- (near U21) JLink-OB Crystal Oscillator and Test Pins
- JLink-OB Reset Switch
- Switch
  Pos A (1-2) = E1 JLINK
  Pos B (2-3) = JTAG Conn

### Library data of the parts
C97 = Cap_225M25VX5R0402_1: as C63 on sheet 7-CODEC
C98 C99 C109 C112-C115 C128 C141 = Cap: as C73 on sheet 7-CODEC
C100 = Cap: as C74 on sheet 7-CODEC
C101-C108 C110 C111 = Cap: as C57-C59 on sheet 7-CODEC
C127 = Cap_SMT: DNI,Cap,100pF,5%,50V,C0G,0402; Manufacturer 1: Kemet; Manufacturer Part Number 1: CBR04C101J3GAC; PCB_Footprint: CC0402
J13 = Hdr_M_1X3_2M54_STRT_UNSHROUD: as J11 on sheet 9-MIPI_CSI
L4 = Inductor: Ind,Unshielded,2.2uH,20%,2.3A,85mOhm,1008(2520); Manufacturer 1: MuRata; Manufacturer Part Number 1: DFE252012F-2R2M=P2; Code_IEC: 2520
R76 = Res3: Res,200R,1%,100ppm,0402; Manufacturer 1: Stackpol; Manufacturer Part Number 1: RMCF0402FT220R; Wattage: 63mW
R78 = Res3: as R60 on sheet 7-CODEC
R102 = Res3: as R91 on sheet 10-MIPI_DSI
R103 = Res3: as R62 on sheet 7-CODEC
R104 = Res3: as R69 on sheet 9-MIPI_CSI
R111 = Res3: Res,0R ohm,Jumper,0402; Manufacturer 1: Stackpol; Manufacturer Part Number 1: RMCF0402ZT0R00; Wattage: 63mW
SW3 = SW-SPDT_Vert-5P: Switch,SPDT, 12V, 50mA, Non-Shorting, 5 Pin PCB Vertical; Manufacturer 1: C&K; Manufacturer Part Number 1: OS102011MS2QN1; Value: SPDT-5Pin
TP44-TP56 = TP_SMPAD: as TP26-TP29 on sheet 7-CODEC
U21 = E7_B0_194BGA: IC,Alif E7 MCU, Rev B silicon,BGA194; Manufacturer 1: Alif Semi; Manufacturer Part Number 1: AE101F4071542LH
Y4 = Xtal_38M4_20PPM6PF_2016-4P_1: Crystal,38.4MHz,20ppm,6.0pF,100ohm,2016-4pin; Manufacturer 1: Murata; Manufacturer Part Number 1: XRCGB38M400F2P00R0; ESR: 100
